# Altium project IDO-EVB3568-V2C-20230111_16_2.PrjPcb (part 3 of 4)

## Sheet P13.SchDoc
size 420 x 297 mm
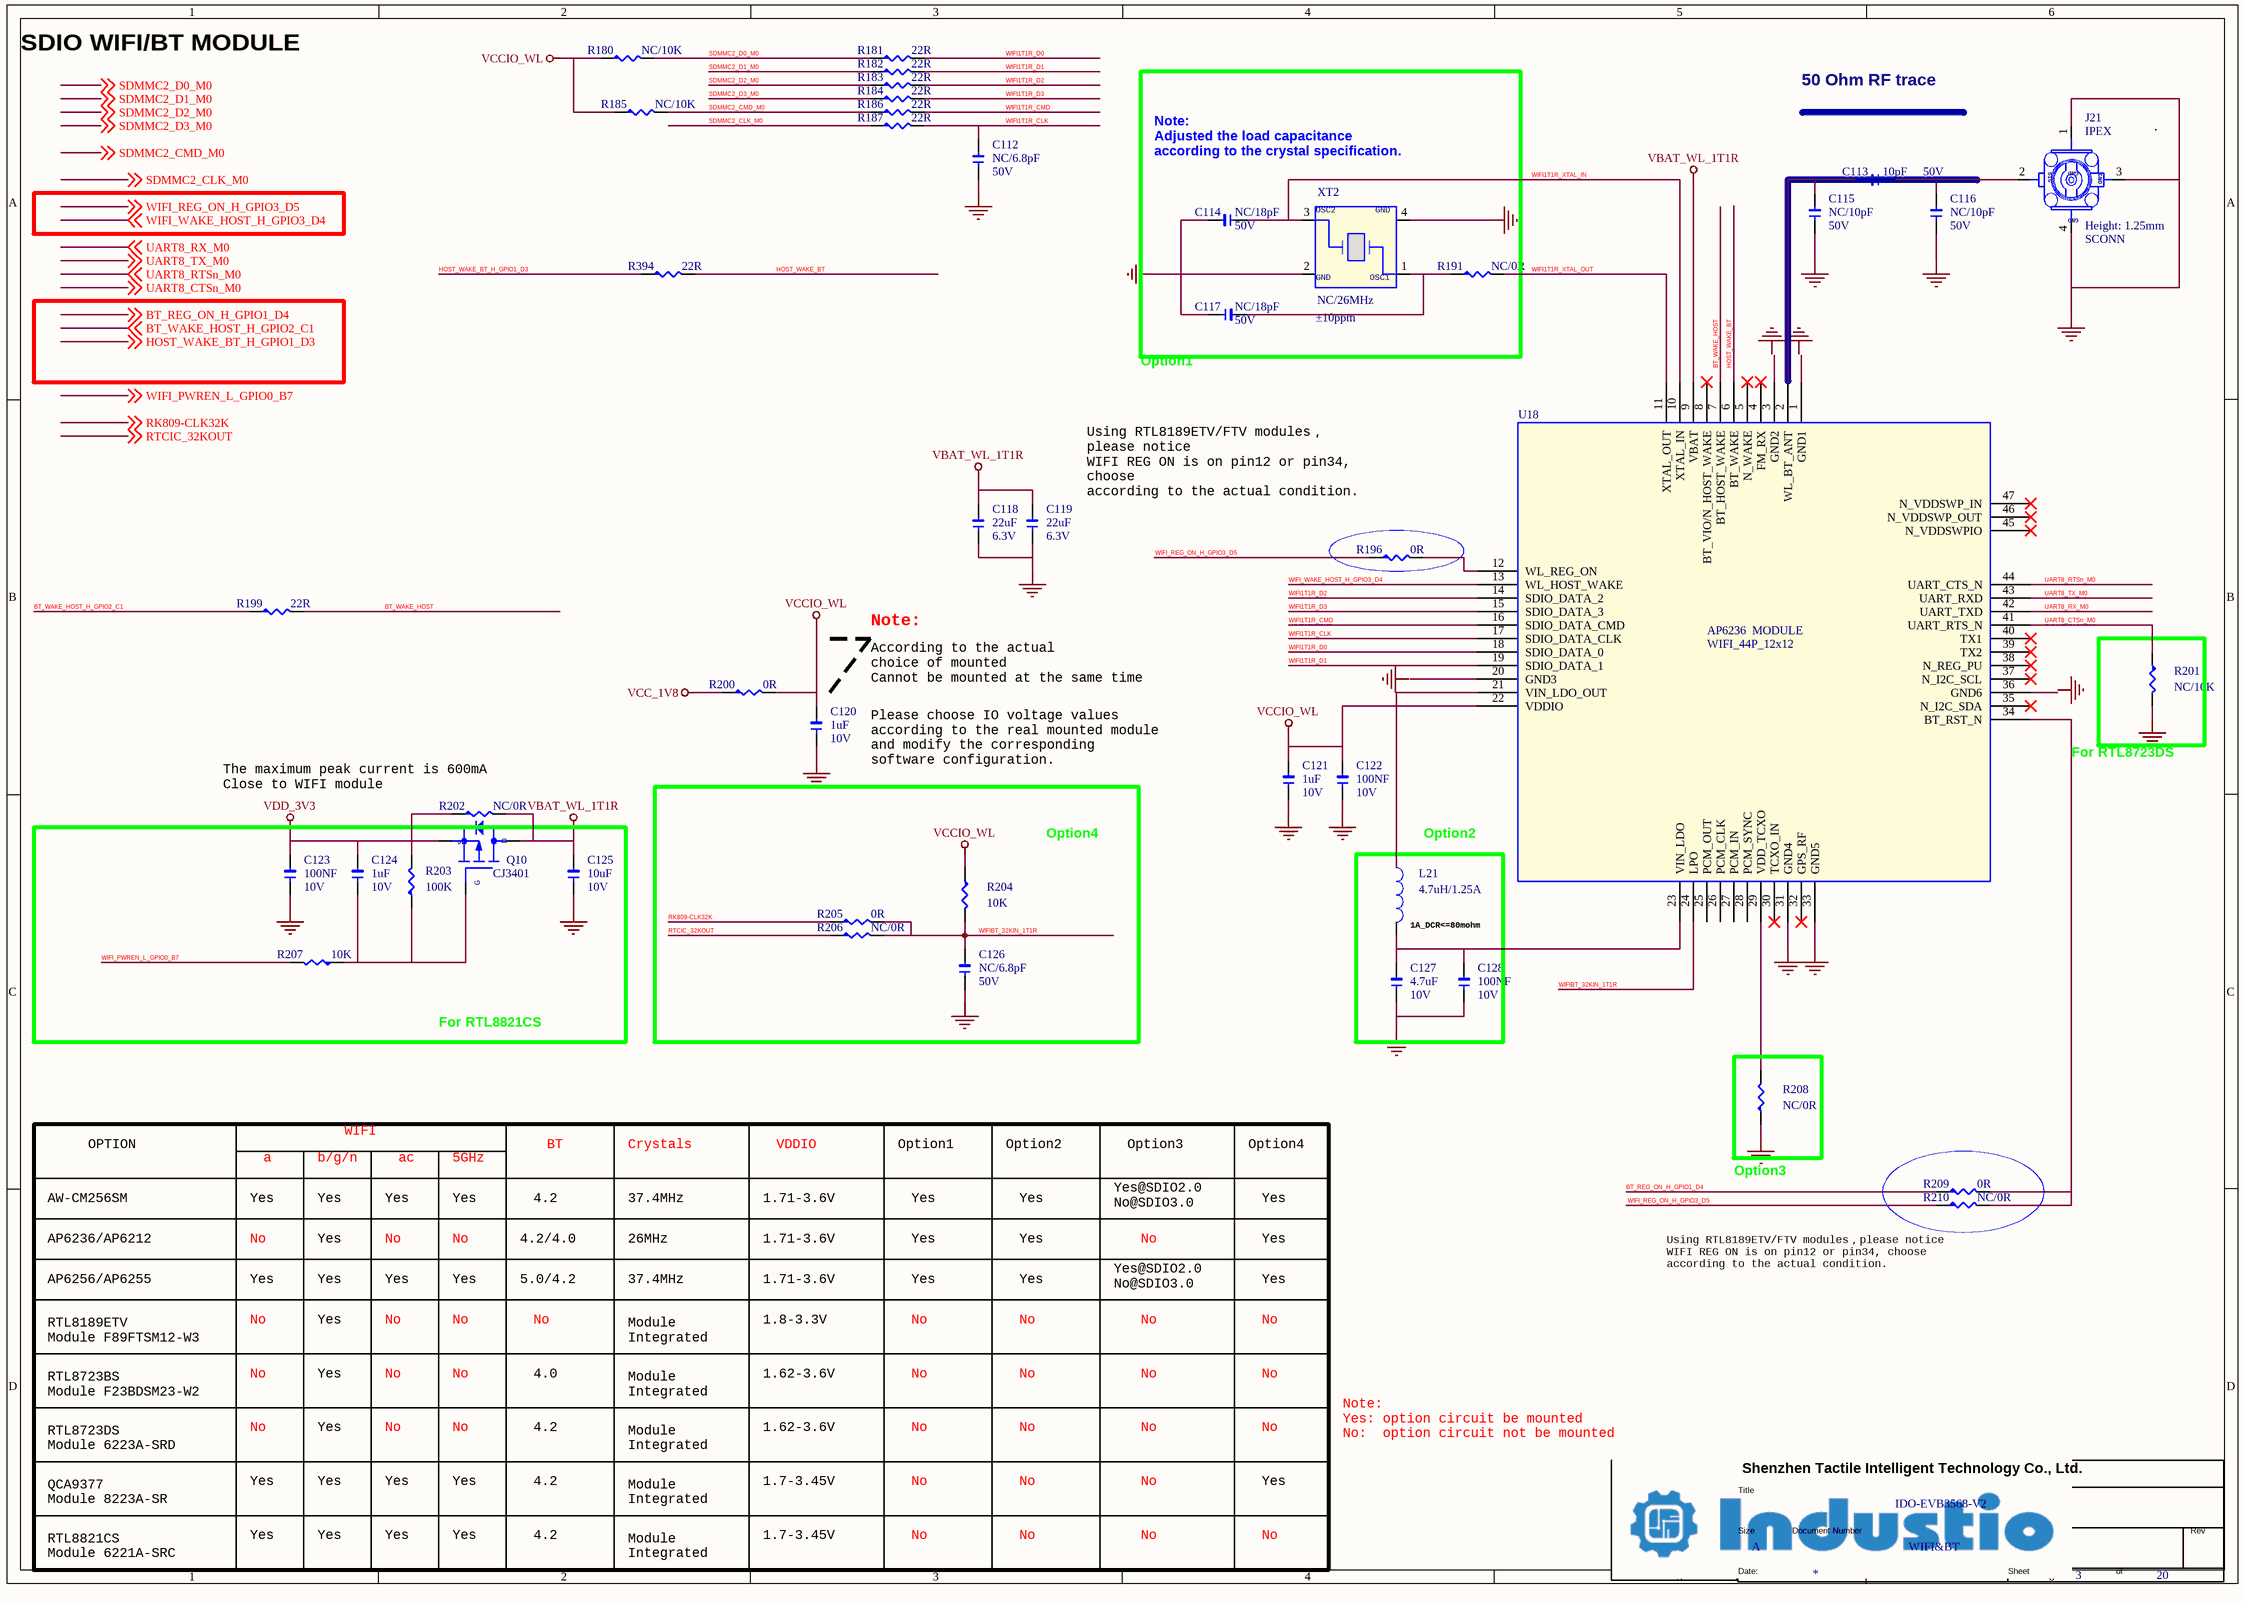
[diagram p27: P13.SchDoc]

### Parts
(Parts that share a designator on the sheet are numbered #1, #2 ... from top to bottom, then left to right.)
*#12  Doc: WIFI&BT  Title: IDO-EVB3568-V2  Page Size: A  Page Number: 3  Page Count: 20  (hidden comment: TitleBlock1)  (graphical)
C112  NC/6.8pF  DSC2: 50V  [1206]
C113  10pF  DSC2: 50V  [1206]
C114  NC/18pF  DSC2: 50V  [1206]
C115  NC/10pF  DSC2: 50V  [1206]
C116  NC/10pF  DSC2: 50V  [1206]
C117  NC/18pF  DSC2: 50V  [1206]
C118  22uF  DSC2: 6.3V  [1206]
C119  22uF  DSC2: 6.3V  [1206]
C120  1uF  DSC2: 10V  [1206]
C121  1uF  DSC2: 10V  [1206]
C122  100NF  DSC2: 10V  [1206]
C123  100NF  DSC2: 10V  [1206]
C124  1uF  DSC2: 10V  [1206]
C125  10uF  DSC2: 10V  [1206]
C126  NC/6.8pF  DSC2: 50V  [1206]
C127  4.7uF  DSC2: 10V  [1206]
C128  100NF  DSC2: 10V  [1206]
J21  IPEX  Material: SCONN  Height: 1.25mm  [IPEX-001E]
L21  4.7uH/1.25A  [IND_252012]
Q10  CJ3401  [SOT23]
R180  NC/10K  [R0402]
R181  22R  [R0402]
R182  22R  [R0402]
R183  22R  [R0402]
R184  22R  [R0402]
R185  NC/10K  [R0402]
R186  22R  [R0402]
R187  22R  [R0402]
R191  NC/0R  [R0402]
R196  0R  [R0402]
R199  22R  [R0402]
R200  0R  [R0402]
R201  NC/10K  [R0402]
R202  NC/0R  [R0805]
R203  100K  [R0402]
R204  10K  [R0402]
R205  0R  [R0402]
R206  NC/0R  [R0402]
R207  10K  [R0402]
R208  NC/0R  [R0402]
R209  0R  [R0402]
R210  NC/0R  [R0402]
R394  22R  [R0402]
U18  AP6236  MODULE  [WIFI_44P_12x12]
XT2  NC/26MHz  DSC2: ±10ppm  [XTAL_32X25_4P]

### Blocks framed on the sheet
Option4: C126 R204-R206
For RTL8821CS: C123-C125 Q10 R203 R207
Option2: C127 C128 L21

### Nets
GND: C112.1 C114.2 C115.1 C116.1 C117.1 C118.1 C119.1 C120.1 C121.1 C122.1 C123.1 C125.1 C126.1 C127.1 C128.1 J21.1(GND1) J21.3(GND2) J21.4(GND3) R201.2 R208.1 U18.31(GND4) U18.33(GND5) XT2.2 XT2.4  [project net EDP_TX_AUXP_]
RTCIC_32KOUT: R206.1 ; off-sheet RTCIC_32KOUT  [project net I2C_SCL_RTC]
VBAT_WL_1T1R: C118.2 C119.2 C125.2 Q10.3(DRAIN) R202.2 U18.9(VBAT)
VCC_1V8: R200.1
VCCIO_WL: C120.2 C121.2 C122.2 R180.1 R185.1 R200.2 R204.1 U18.22(VDDIO)
VDD_3V3: C123.2 C124.2 Q10.2(SOURCE) R202.1 R203.2
BT_REG_ON_H_GPIO1_D4: R209.1 ; off-sheet BT_REG_ON_H_GPIO1_D4
BT_WAKE_HOST: R199.2 U18.7(BT_HOST_WAKE)
BT_WAKE_HOST_H_GPIO2_C1: R199.1 ; off-sheet BT_WAKE_HOST_H_GPIO2_C1
HOST_WAKE_BT: R394.2 U18.6(BT_WAKE)
HOST_WAKE_BT_H_GPIO1_D3: R394.1 ; off-sheet HOST_WAKE_BT_H_GPIO1_D3
RK809-CLK32K: R205.1 ; off-sheet RK809-CLK32K
SDMMC2_CLK_M0: R187.1 ; off-sheet SDMMC2_CLK_M0
SDMMC2_CMD_M0: R185.2 R186.1 ; off-sheet SDMMC2_CMD_M0
SDMMC2_D0_M0: R180.2 R181.1 ; off-sheet SDMMC2_D0_M0
SDMMC2_D1_M0: R182.1 ; off-sheet SDMMC2_D1_M0
SDMMC2_D2_M0: R183.1 ; off-sheet SDMMC2_D2_M0
SDMMC2_D3_M0: R184.1 ; off-sheet SDMMC2_D3_M0
UART8_CTSn_M0: R201.1 U18.41(UART_RTS_N) ; off-sheet UART8_CTSn_M0
UART8_RTSn_M0: U18.44(UART_CTS_N) ; off-sheet UART8_RTSn_M0
UART8_RX_M0: U18.42(UART_TXD) ; off-sheet UART8_RX_M0
UART8_TX_M0: U18.43(UART_RXD) ; off-sheet UART8_TX_M0
WIFI1T1R_CLK: C112.2 R187.2 U18.17(SDIO_DATA_CLK)
WIFI1T1R_CMD: R186.2 U18.16(SDIO_DATA_CMD)
WIFI1T1R_D0: R181.2 U18.18(SDIO_DATA_0)
WIFI1T1R_D1: R182.2 U18.19(SDIO_DATA_1)
WIFI1T1R_D2: R183.2 U18.14(SDIO_DATA_2)
WIFI1T1R_D3: R184.2 U18.15(SDIO_DATA_3)
WIFI1T1R_XTAL_IN: C114.1 U18.10(XTAL_IN) XT2.3
WIFI1T1R_XTAL_OUT: R191.2 U18.11(XTAL_OUT)
WIFI_PWREN_L_GPIO0_B7: R207.2 ; off-sheet WIFI_PWREN_L_GPIO0_B7
WIFI_REG_ON_H_GPIO3_D5: R196.1 R210.1 ; off-sheet WIFI_REG_ON_H_GPIO3_D5
WIFI_WAKE_HOST_H_GPIO3_D4: U18.13(WL_HOST_WAKE) ; off-sheet WIFI_WAKE_HOST_H_GPIO3_D4
WIFIBT_32KIN_1T1R: C126.2 R204.2 R205.2 R206.2 U18.24(LPO)
NetC113_1: C113.1 C116.2 J21.2(SIG)
NetC113_2: C113.2 C115.2 U18.2(WL_BT_ANT)
NetC117_2: C117.2 R191.1 XT2.1
NetC124_1: C124.1 Q10.1(GATE) R203.1 R207.1
NetC127_2: C127.2 C128.2 L21.2 U18.23(VIN_LDO)
NetL21_1: L21.1 U18.21(VIN_LDO_OUT)
NetR196_2: R196.2 U18.12(WL_REG_ON)
NetR208_2: R208.2 U18.29(VDD_TCXO)
NetR209_2: R209.2 R210.2 U18.34(BT_RST_N)

Not connected (* = marked no-connect by the designer): U18 1(GND1) 3(GND2) 4(FM_RX)* 5(N_WAKE)* 8(BT_VIO/N_HOST_WAKE)* 20(GND3) 25(PCM_OUT) 26(PCM_CLK) 27(PCM_IN) 28(PCM_SYNC) 30(TCXO_IN)* 32(GPS_RF)* 35(N_I2C_SDA)* 36(GND6) 37(N_I2C_SCL)* 38(N_REG_PU)* 39(TX2)* 40(TX1)* 45(N_VDDSWPIO)* 46(N_VDDSWP_OUT)* 47(N_VDDSWP_IN)*

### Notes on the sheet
- SDIO WIFI/BT MODULE
- Note:
  Adjusted the load capacitance
  according to the crystal specification.
- 50 Ohm RF trace
- (near C117) Option1
- Using RTL8189ETV/FTV modules，
  please notice
  WIFI REG ON is on pin12 or pin34,
  choose
  according to the actual condition.
- According to the actual
  choice of mounted
  Cannot be mounted at the same time
- Note:
- (near C121) Please choose IO voltage values
  according to the real mounted module
  and modify the corresponding
  software configuration.
- (near R202) The maximum peak current is 600mA
  Close to WIFI module
- For RTL8723DS
- (near L21) 1A_DCR<=80mohm
- WIFI
- AW-CM256SM
- OPTION
- Yes
- a
- b/g/n
- ac
- 5GHz
- 4.2
- BT
- Crystals
- 37.4MHz
- 1.71-3.6V
- VDDIO
- Option1
- Option2
- Yes@SDIO2.0
  No@SDIO3.0
- Option3
- Option4
- AP6236/AP6212
- No
- 4.2/4.0
- 26MHz
- Using RTL8189ETV/FTV modules，please notice
  WIFI REG ON is on pin12 or pin34, choose
  according to the actual condition.
- AP6256/AP6255
- RTL8189ETV
  Module F89FTSM12-W3
- 5.0/4.2
- Module
  Integrated
- 1.8-3.3V
- RTL8723BS
  Module F23BDSM23-W2
- 4.0
- 1.62-3.6V
- (near *#12) Note:
  Yes: option circuit be mounted
  No:  option circuit not be mounted
- RTL8723DS
  Module 6223A-SRD
- QCA9377
  Module 8223A-SR
- RTL8821CS
  Module 6221A-SRC
- 1.7-3.45V
- Labels drawn without touching a wire or pin: GND

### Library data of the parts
C112 = C-0402_Dup2: Part Number: C020102120018; Part Name: 贴片电容; Manufacture: 三星¦国巨¦村田; ERP Number: 1010200056; DSC1: ±0.25PF; DSC3: C0G; ID: 18; PCB Footprint: C0402
C113 = C-0402_Dup2: Manufacture: 三星¦国巨¦村田; Part Name: 贴片电容; Part Number: C020102120021; ID: 21; DSC3: C0G; DSC1: ±5%; ERP Number: 1010200151; PCB Footprint: C0402
C114 C117 = C-0402_Dup2: Manufacture: 三星¦国巨¦村田; Part Name: 贴片电容; Part Number: C020102120027; PCB Footprint: C0402; ID: 27; DSC3: C0G; DSC1: ±5%; ERP Number: 1010200091
C115 C116 = C-0402_Dup2: Part Number: C020102120021; Part Name: 贴片电容; Manufacture: 三星¦国巨¦村田; ERP Number: 1010200151; DSC1: ±5%; DSC3: C0G; ID: 21; PCB Footprint: C0402
C118 C119 = C-0603_Dup2: Manufacture: 三星¦国巨¦村田; Part Name: 贴片电容; Part Number: C020102120072; ID: 72; DSC3: X5R; DSC1: ±20%; ERP Number: 1010200133; PCB Footprint: C0603
C120 C124 = C-0402_Dup2: Part Number: C020102120064; Part Name: 贴片电容; Manufacture: 三星¦国巨¦村田; ERP Number: 1010200054; DSC1: ±10%; DSC3: X5R; ID: 64; PCB Footprint: C0402
C121 = C-0402_Dup2: Manufacture: 三星¦国巨¦村田; Part Name: 贴片电容; Part Number: C020102120064; ID: 64; DSC3: X5R; DSC1: ±10%; ERP Number: 1010200054; PCB Footprint: C0402
C122 C128 = C-0402_Dup2: Manufacture: 三星¦国巨¦村田; Part Name: 贴片电容; Part Number: C020102120060; ID: 60; DSC3: X7R; DSC1: ±10%; PCB Footprint: C0402
C123 = C-0402_Dup2: Part Number: C020102120060; Part Name: 贴片电容; Manufacture: 三星¦国巨¦村田; DSC1: ±10%; DSC3: X7R; ID: 60; PCB Footprint: C0402
C125 = C-0603_Dup2: Manufacture: 三星¦国巨¦村田; Part Name: 贴片电容; Part Number: C020102120071; ID: 71; DSC3: X5R; DSC1: ±20%; ERP Number: 1010200076; PCB Footprint: C0603
C126 = C-0402_Dup2: Manufacture: 三星¦国巨¦村田; Part Name: 贴片电容; Part Number: C020102120018; ID: 18; DSC3: C0G; DSC1: ±0.25PF; ERP Number: 1010200056; PCB Footprint: C0402
C127 = C-0402_Dup2: Manufacture: 三星¦国巨¦村田; Part Name: 贴片电容; Part Number: C020102120067; ID: 67; DSC3: X5R; DSC1: ±20%; PCB Footprint: C0402
J21 = RF-IPEX-20279: SMD micro Coaxial Connector Receptacle vertial; Part Name: IPEX座; Part Number: J110103040001; Pack_Type: MHF-20279; ID: 1; DSC2: 贴片; DSC1: IPEX-20279-001E-01 板端贴片天线座 U.LF接头
L21 = L-IND: Part Name: 功率电感; Manufacture: 宗成¦长江微电¦顺络; DSC1: ±20%; DSC2: Isat=1.6A; DSC3: Irms=1.25A; DSC4: 260mΩ; DSC5: 2.5*2.0*1.2mm; DSC6: WPN252012H4R7MT(顺络); DSC7: FHD252012S-4R7MT(长江微电); DSC8: ZCRH252012-4.7uH-M(宗成); ID: 54
Q10 = P-MOS: Manufacture: 长电; Part Number: C030202190001; ID: 1; DSC5: pd=350mW; DSC4: Vgs=±12V; DSC3: Vgs(th)=1.3V; DSC2: Id=-4.2A; DSC1: Vds=-30V; ERP Number: 1010800001
R180 R185 R201 R204 R207 = R-0402_Dup4: Part Name: 贴片电阻; Part Number: C011002080328; ERP Number: 1010200096; DSC1: ±5%; DSC2: 1/16W; ID: 328
R181-R184 R186 R187 R199 R394 = R-0402_Dup4: Part Number: C011002080262; Part Name: 贴片电阻; ID: 262; DSC2: 1/16W; DSC1: ±5%; ERP Number: 1010200173
R191 R196 R200 R206 R209 = R-0402_Dup4: Part Number: C011002080217; Part Name: 贴片电阻; ID: 217; DSC2: 1/16W; DSC1: ±5%; ERP Number: 1010200100
R202 = R-0805_Dup2: Part Number: C011002081448; Part Name: 贴片电阻; ID: 1,448; DSC2: 1/8W; DSC1: ±1%; ERP Number: 1010200199
R203 = R-0402_Dup4: Part Number: C011002080353; Part Name: 贴片电阻; ID: 353; DSC2: 1/16W; DSC1: ±5%; ERP Number: 1010200103
R205 R208 R210 = R-0402_Dup4: Part Name: 贴片电阻; Part Number: C011002080217; ERP Number: 1010200100; DSC1: ±5%; DSC2: 1/16W; ID: 217
U18 = MODULE_AP6XXX: WiFi+Bluetooth 4.0(HS)+FM Rx; Manufacturer PN: AP6335; Manufacturer: Ampak（正基科技）; Priority: A
XT2 = XTAL-4P: Manufacture: 爱普生; Part Number: C050102290007; Part Name: 贴片无源晶振; CLASS: IC; ID: 7; DSC5: 3.2*2.5mm 4P; DSC4: -40℃~+85℃; DSC3: 12pF; DSC1: 40Ω; ERP Number: 1010700036

## Sheet P14.SchDoc
size 594 x 420 mm
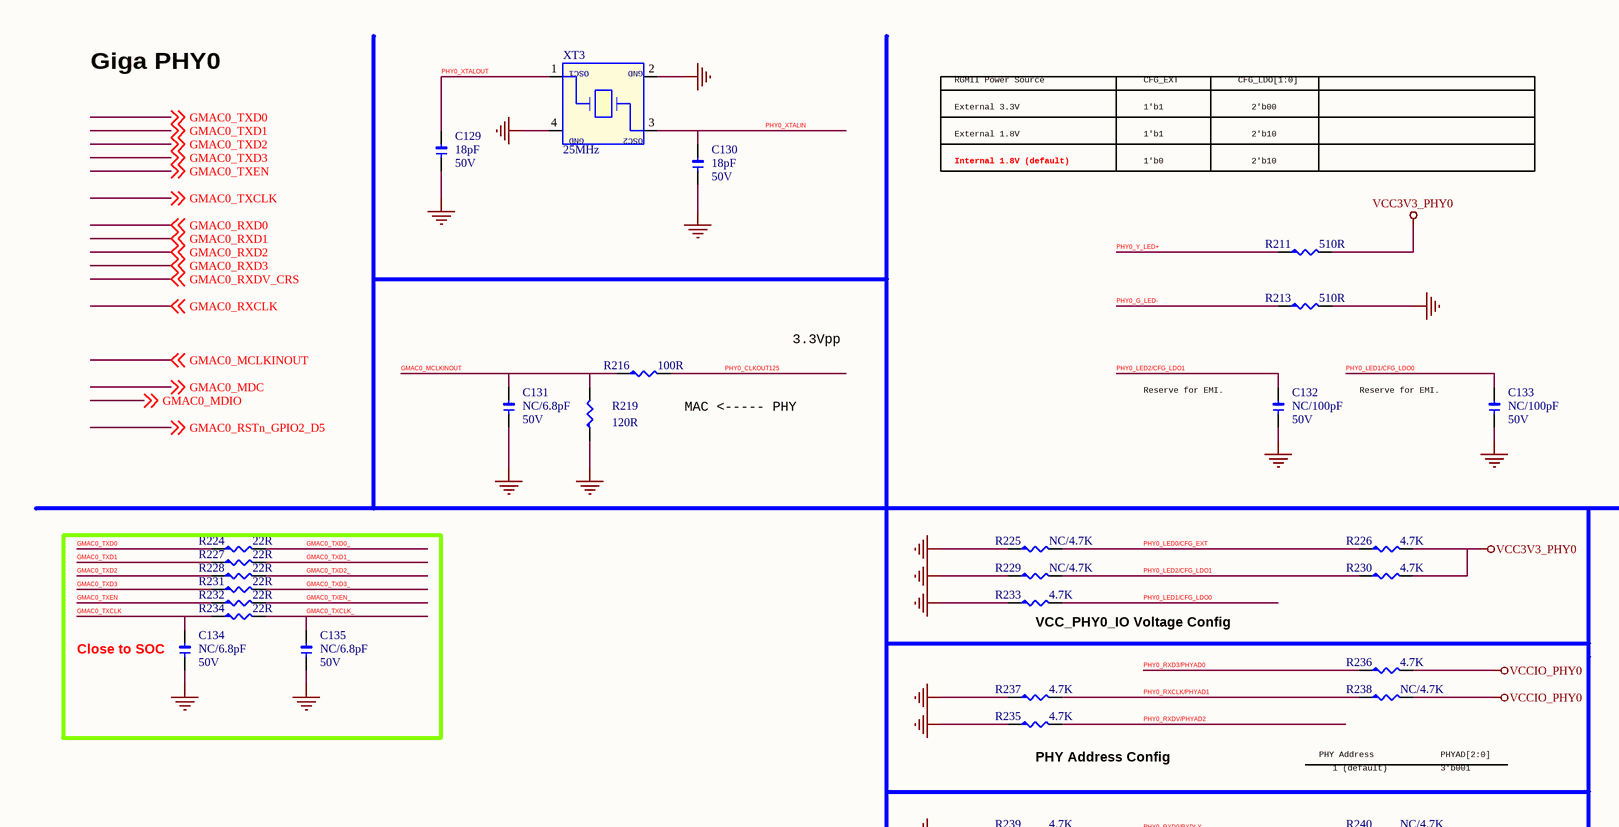
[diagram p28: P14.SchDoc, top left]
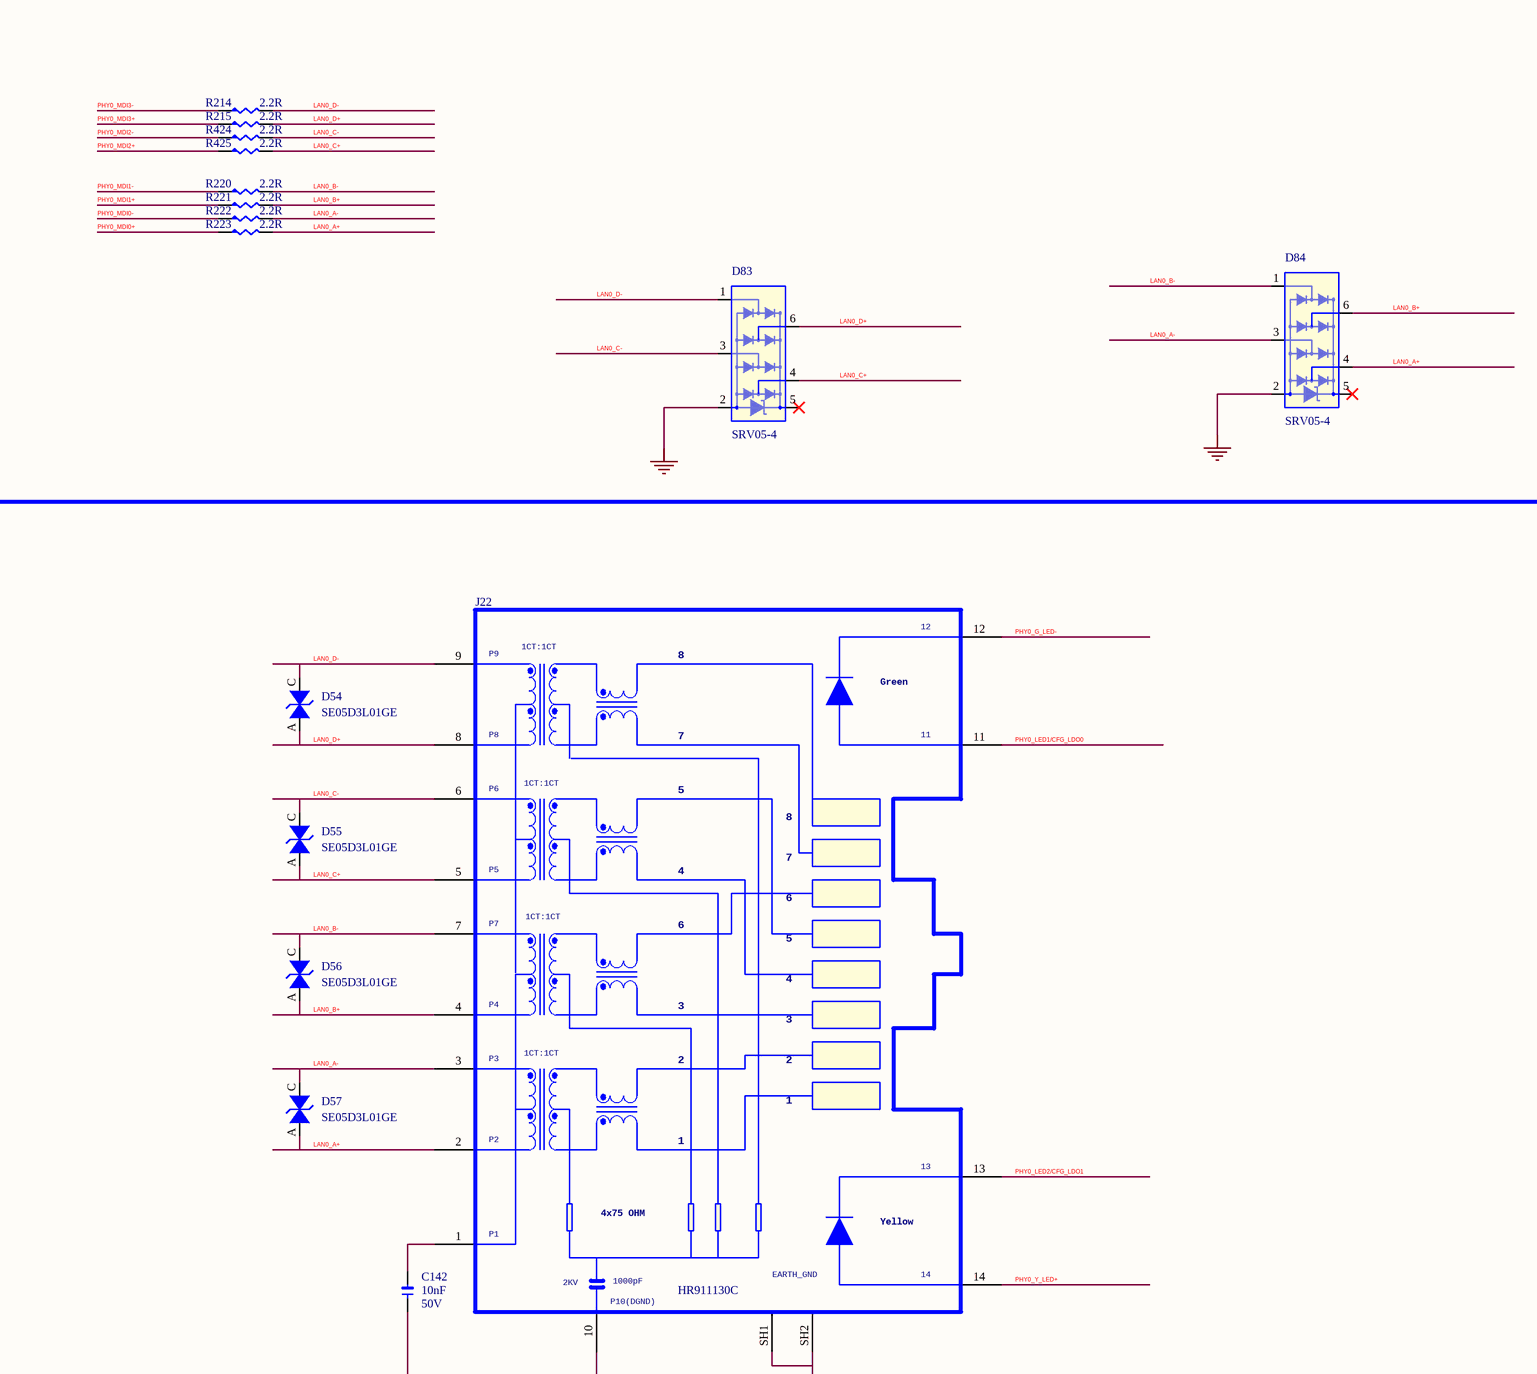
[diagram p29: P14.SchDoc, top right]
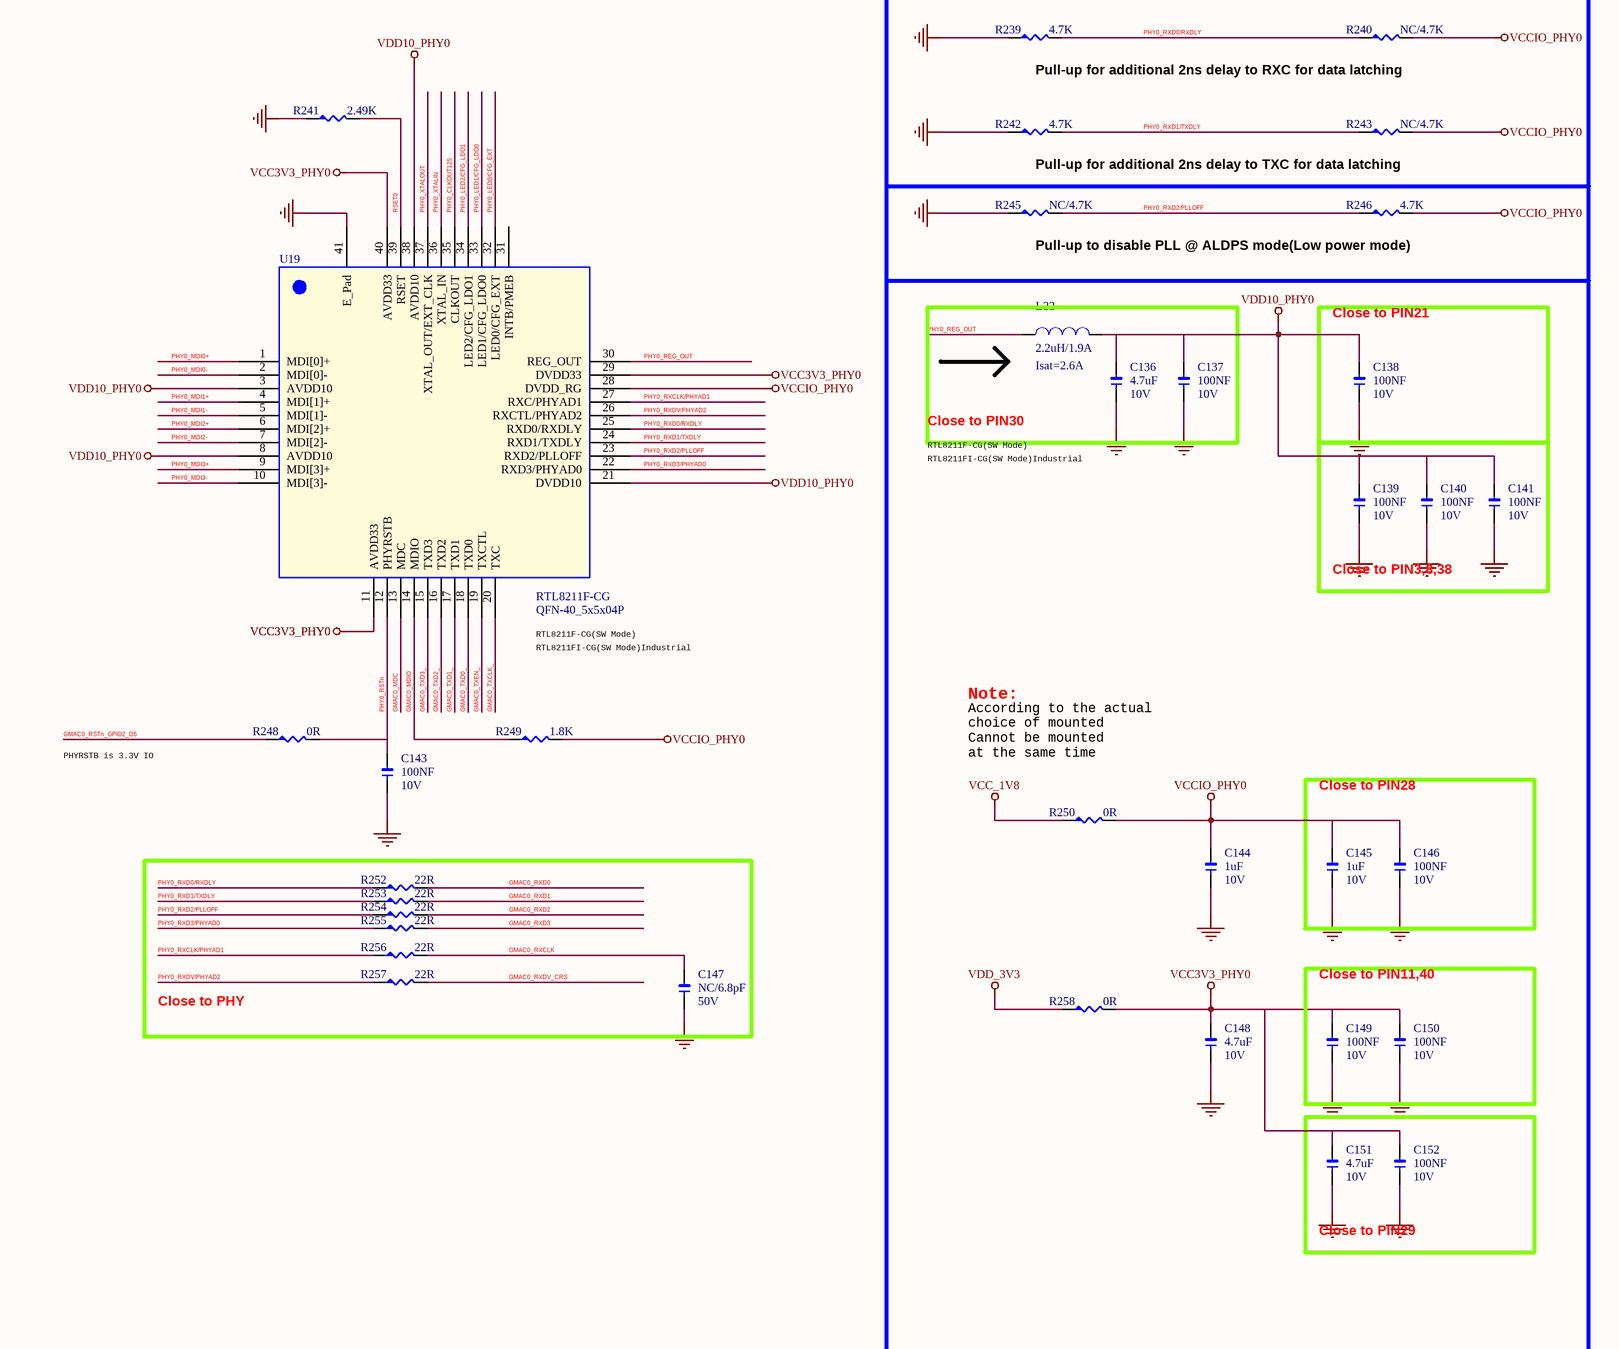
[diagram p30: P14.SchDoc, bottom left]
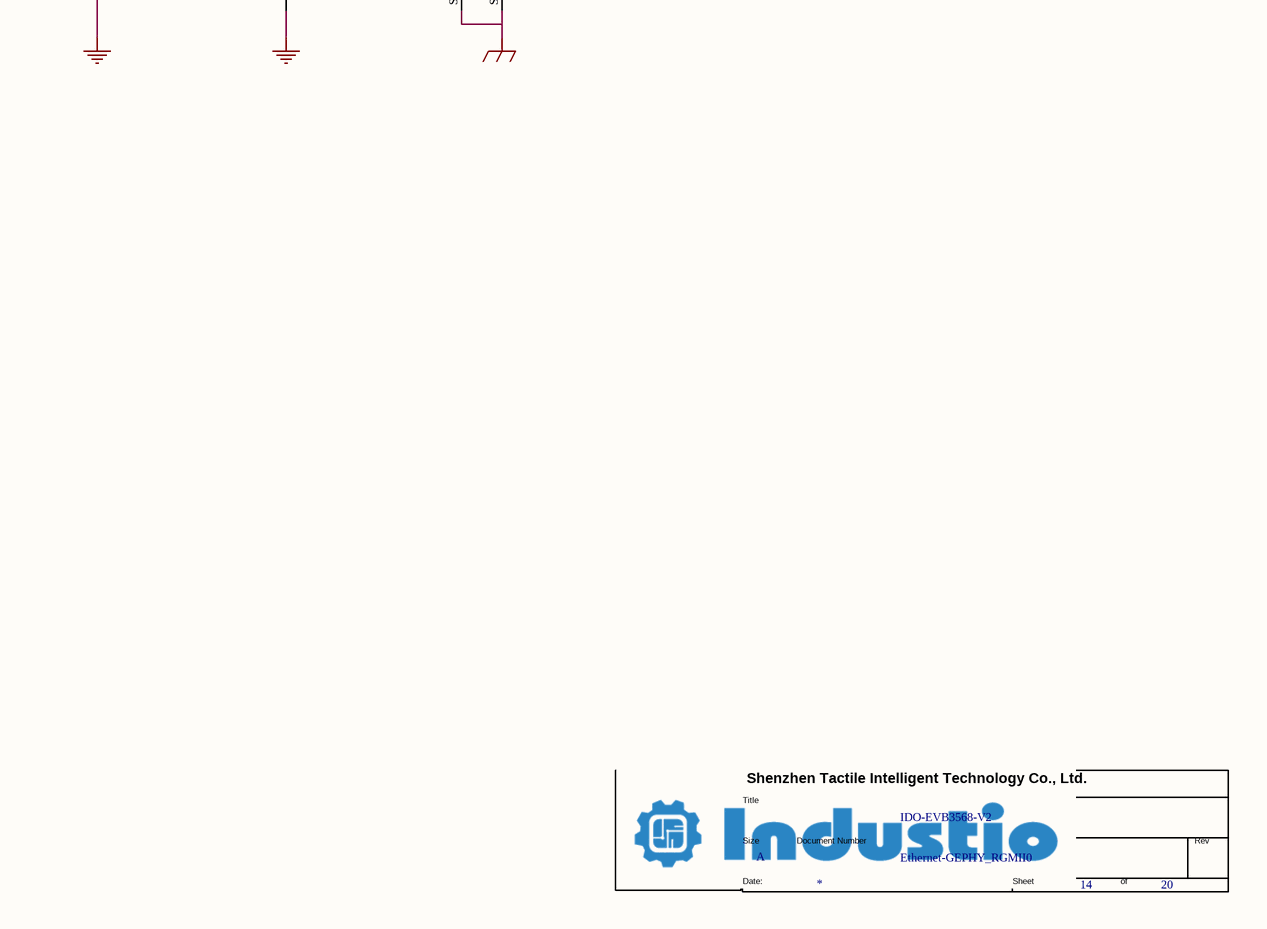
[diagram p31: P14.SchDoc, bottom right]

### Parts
(Parts that share a designator on the sheet are numbered #1, #2 ... from top to bottom, then left to right.)
*#13  Doc: Ethernet-GEPHY_RGMII0  Title: IDO-EVB3568-V2  Page Size: A  Page Number: 14  Page Count: 20  (hidden comment: TitleBlock1)  (graphical)
C129  18pF  DSC2: 50V  [1206]
C130  18pF  DSC2: 50V  [1206]
C131  NC/6.8pF  DSC2: 50V  [1206]
C132  NC/100pF  DSC2: 50V  [1206]
C133  NC/100pF  DSC2: 50V  [1206]
C134  NC/6.8pF  DSC2: 50V  [1206]
C135  NC/6.8pF  DSC2: 50V  [1206]
C136  4.7uF  DSC2: 10V  [1206]
C137  100NF  DSC2: 10V  [1206]
C138  100NF  DSC2: 10V  [1206]
C139  100NF  DSC2: 10V  [1206]
C140  100NF  DSC2: 10V  [1206]
C141  100NF  DSC2: 10V  [1206]
C142  10nF  DSC2: 50V  [1206]
C143  100NF  DSC2: 10V  [1206]
C144  1uF  DSC2: 10V  [1206]
C145  1uF  DSC2: 10V  [1206]
C146  100NF  DSC2: 10V  [1206]
C147  NC/6.8pF  DSC2: 50V  [1206]
C148  4.7uF  DSC2: 10V  [1206]
C149  100NF  DSC2: 10V  [1206]
C150  100NF  DSC2: 10V  [1206]
C151  4.7uF  DSC2: 10V  [1206]
C152  100NF  DSC2: 10V  [1206]
D54  SE05D3L01GE  [SOD323]
D55  SE05D3L01GE  [SOD323]
D56  SE05D3L01GE  [SOD323]
D57  SE05D3L01GE  [SOD323]
D83  SRV05-4  [SOT23-6]
D84  SRV05-4  [SOT23-6]
J22  HR911130C  [RJ45-TH_HR911130A]
L22  2.2uH/1.9A  DSC2: Isat=2.6A  [IND_252012]
R211  510R  [R0402]
R213  510R  [R0402]
R214  2.2R  [R0402]
R215  2.2R  [R0402]
R216  100R  [R0402]
R219  120R  [R0402]
R220  2.2R  [R0402]
R221  2.2R  [R0402]
R222  2.2R  [R0402]
R223  2.2R  [R0402]
R224  22R  [R0402]
R225  NC/4.7K  [R0402]
R226  4.7K  [R0402]
R227  22R  [R0402]
R228  22R  [R0402]
R229  NC/4.7K  [R0402]
R230  4.7K  [R0402]
R231  22R  [R0402]
R232  22R  [R0402]
R233  4.7K  [R0402]
R234  22R  [R0402]
R235  4.7K  [R0402]
R236  4.7K  [R0402]
R237  4.7K  [R0402]
R238  NC/4.7K  [R0402]
R239  4.7K  [R0402]
R240  NC/4.7K  [R0402]
R241  2.49K  [R0402]
R242  4.7K  [R0402]
R243  NC/4.7K  [R0402]
R245  NC/4.7K  [R0402]
R246  4.7K  [R0402]
R248  0R  [R0402]
R249  1.8K  [R0402]
R250  0R  [R0402]
R252  22R  [R0402]
R253  22R  [R0402]
R254  22R  [R0402]
R255  22R  [R0402]
R256  22R  [R0402]
R257  22R  [R0402]
R258  0R  [R0402]
R424  2.2R  [R0402]
R425  2.2R  [R0402]
U19  RTL8211F-CG  PCB Footprint: QFN-40_5x5x04P  [QFN40_5R00X5R00X0R80_T]
XT3  25MHz  [xtal_32x25_4p]

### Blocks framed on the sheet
Close to SOC: C134 C135 R224 R227 R228 R231 R232 R234
Close to PIN30: C136 C137 L22
Close to PIN21: C138
Close to PIN3,8,38: C139-C141
Close to PIN28: C145 C146
Close to PHY: C147 R252-R257
Close to PIN11,40: C149 C150
Close to PIN29: C151 C152

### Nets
GND: C129.1 C130.1 C131.1 C132.1 C133.1 C134.1 C135.1 C136.1 C137.1 C138.1 C139.1 C140.1 C141.1 C142.1 C143.1 C144.1 C145.1 C146.1 C147.1 C148.1 C149.1 C150.1 C151.1 C152.1 D83.2 D84.2 J22.10(GND) R213.2 R219.1 R225.1 R229.1 R233.1 R235.1 R237.1 R239.1 R241.1 R242.1 R245.1 U19.41(E_Pad) XT3.2 XT3.4  [project net EDP_TX_AUXP_]
GND_EARTH: J22.SH1 J22.SH2
VCC3V3_PHY0: C148.2 C149.2 C150.2 C151.2 C152.2 R211.2 R226.2 R230.2 R258.2 U19.11(AVDD33) U19.29(DVDD33) U19.40(AVDD33)
VCC_1V8: R250.1
VCCIO_PHY0: C144.2 C145.2 C146.2 R236.2 R238.2 R240.2 R243.2 R246.2 R249.2 R250.2 U19.28(DVDD_RG)
VDD10_PHY0: C136.2 C137.2 C138.2 C139.2 C140.2 C141.2 L22.2 U19.3(AVDD10) U19.8(AVDD10) U19.21(DVDD10) U19.38(AVDD10)
VDD_3V3: R258.1
GMAC0_MCLKINOUT: C131.2 R216.1 R219.2 ; off-sheet GMAC0_MCLKINOUT
GMAC0_MDC: U19.13(MDC) ; off-sheet GMAC0_MDC
GMAC0_MDIO: R249.1 U19.14(MDIO) ; off-sheet GMAC0_MDIO
GMAC0_RSTn_GPIO2_D5: R248.1 ; off-sheet GMAC0_RSTn_GPIO2_D5
GMAC0_RXCLK: C147.2 R256.2 ; off-sheet GMAC0_RXCLK
GMAC0_RXD0: R252.2 ; off-sheet GMAC0_RXD0
GMAC0_RXD1: R253.2 ; off-sheet GMAC0_RXD1
GMAC0_RXD2: R254.2 ; off-sheet GMAC0_RXD2
GMAC0_RXD3: R255.2 ; off-sheet GMAC0_RXD3
GMAC0_RXDV_CRS: R257.2 ; off-sheet GMAC0_RXDV_CRS
GMAC0_TXCLK: C134.2 R234.1 ; off-sheet GMAC0_TXCLK
GMAC0_TXCLK_: C135.2 R234.2 U19.20(TXC)
GMAC0_TXD0: R224.1 ; off-sheet GMAC0_TXD0
GMAC0_TXD0_: R224.2 U19.18(TXD0)
GMAC0_TXD1: R227.1 ; off-sheet GMAC0_TXD1
GMAC0_TXD1_: R227.2 U19.17(TXD1)
GMAC0_TXD2: R228.1 ; off-sheet GMAC0_TXD2
GMAC0_TXD2_: R228.2 U19.16(TXD2)
GMAC0_TXD3: R231.1 ; off-sheet GMAC0_TXD3
GMAC0_TXD3_: R231.2 U19.15(TXD3)
GMAC0_TXEN: R232.1 ; off-sheet GMAC0_TXEN
GMAC0_TXEN_: R232.2 U19.19(TXCTL)
LAN0_A+: D57.A(I/O2) D84.4 J22.2(MDI_0+) R223.2
LAN0_A-: D57.C(I/O1) D84.3 J22.3(MDI_0-) R222.2
LAN0_B+: D56.A(I/O2) D84.6 J22.4(MDI_1+) R221.2
LAN0_B-: D56.C(I/O1) D84.1 J22.7(MDI_1-) R220.2
LAN0_C+: D55.A(I/O2) D83.4 J22.5(MDI_2+) R425.2
LAN0_C-: D55.C(I/O1) D83.3 J22.6(MDI_2-) R424.2
LAN0_D+: D54.A(I/O2) D83.6 J22.8(MDI_3+) R215.2
LAN0_D-: D54.C(I/O1) D83.1 J22.9(MDI_3-) R214.2
PHY0_CLKOUT125: R216.2 U19.35(CLKOUT)
PHY0_G_LED-: J22.12(G_LED-) R213.1
PHY0_LED0/CFG_EXT: R225.2 R226.1 U19.32(LED0/CFG_EXT)
PHY0_LED1/CFG_LDO0: C133.2 J22.11(G_LED+) R233.2 U19.33(LED1/CFG_LDO0)
PHY0_LED2/CFG_LDO1: C132.2 J22.13(Y_LED-) R229.2 R230.1 U19.34(LED2/CFG_LDO1)
PHY0_MDI0+: R223.1 U19.1(MDI[0]+)
PHY0_MDI0-: R222.1 U19.2(MDI[0]-)
PHY0_MDI1+: R221.1 U19.4(MDI[1]+)
PHY0_MDI1-: R220.1 U19.5(MDI[1]-)
PHY0_MDI2+: R425.1 U19.6(MDI[2]+)
PHY0_MDI2-: R424.1 U19.7(MDI[2]-)
PHY0_MDI3+: R215.1 U19.9(MDI[3]+)
PHY0_MDI3-: R214.1 U19.10(MDI[3]-)
PHY0_REG_OUT: L22.1 U19.30(REG_OUT)
PHY0_RSTn: C143.2 R248.2 U19.12(PHYRSTB)
PHY0_RXCLK/PHYAD1: R237.2 R238.1 R256.1 U19.27(RXC/PHYAD1)
PHY0_RXD0/RXDLY: R239.2 R240.1 R252.1 U19.25(RXD0/RXDLY)
PHY0_RXD1/TXDLY: R242.2 R243.1 R253.1 U19.24(RXD1/TXDLY)
PHY0_RXD2/PLLOFF: R245.2 R246.1 R254.1 U19.23(RXD2/PLLOFF)
PHY0_RXD3/PHYAD0: R236.1 R255.1 U19.22(RXD3/PHYAD0)
PHY0_RXDV/PHYAD2: R235.2 R257.1 U19.26(RXCTL/PHYAD2)
PHY0_XTALIN: C130.2 U19.36(XTAL_IN) XT3.3
PHY0_XTALOUT: C129.2 U19.37(XTAL_OUT/EXT_CLK) XT3.1
PHY0_Y_LED+: J22.14(Y_LED+) R211.1
RSET0: R241.2 U19.39(RSET)
NetC142_2: C142.2 J22.1(CT1/2/3/4)

Not connected (* = marked no-connect by the designer): D83 5*; D84 5*; U19 31(INTB/PMEB)

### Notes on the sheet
- Giga PHY0
- RGMII Power Source
- External 3.3V
- CFG_EXT
- 1'b1
- CFG_LDO[1:0]
- 2'b00
- External 1.8V
- Internal 1.8V (default)
- 1'b0
- 2'b10
- 3.3Vpp
- (near R216) MAC <----- PHY
- Reserve for EMI.
- (near R233) VCC_PHY0_IO Voltage Config
- (near R235) PHY Address Config
- PHY Address
- 1 (default)
- PHYAD[2:0]
- 3'b001
- Pull-up for additional 2ns delay to RXC for data latching
- Pull-up for additional 2ns delay to TXC for data latching
- Pull-up to disable PLL @ ALDPS mode(Low power mode)
- RTL8211F-CG(SW Mode)
- RTL8211FI-CG(SW Mode)Industrial
- Note:
- (near R250) According to the actual
  choice of mounted
  Cannot be mounted
  at the same time
- PHYRSTB is 3.3V IO

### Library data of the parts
C129 C130 = C-0402_Dup2: Part Number: C020102120027; Part Name: 贴片电容; Manufacture: 三星¦国巨¦村田; ERP Number: 1010200091; DSC1: ±5%; DSC3: C0G; ID: 27; PCB Footprint: C0402
C131 C147 = C-0402_Dup2: as C126 on sheet P13
C132 = C-0402_Dup2: Manufacture: 三星¦国巨¦村田; Part Name: 贴片电容; Part Number: C020102120040; ID: 40; DSC3: C0G; DSC1: ±5%; ERP Number: 1010200152; PCB Footprint: C0402
C133 = C-0402_Dup2: Part Number: C020102120040; Part Name: 贴片电容; Manufacture: 三星¦国巨¦村田; ERP Number: 1010200152; DSC1: ±5%; DSC3: C0G; ID: 40; PCB Footprint: C0402
C134 C135 = C-0402_Dup2: as C112 on sheet P13
C136 = C-0402_Dup2: as C127 on sheet P13
C137-C141 C143 = C-0402_Dup2: as C123 on sheet P13
C142 = C-0402_Dup2: Part Number: C020102120057; Part Name: 贴片电容; Manufacture: 三星¦国巨¦村田; ERP Number: 1010200077; DSC1: ±10%; DSC3: X7R; ID: 57; PCB Footprint: C0402
C144 C145 = C-0402_Dup2: as C120 on sheet P13
C146 C149 C150 C152 = C-0402_Dup2: as C122 on sheet P13
C148 C151 = C-0402_Dup2: Part Number: C020102120067; Part Name: 贴片电容; Manufacture: 三星¦国巨¦村田; DSC1: ±20%; DSC3: X5R; ID: 67; PCB Footprint: C0402
D54 D57 = DI-TVS-D: ESD 0402; Part Number: C040505124709; Manufacture P/N: MLVG04021R0UV18; Manufacturer: INPAQ; Manufacture: 硕凯; PN Type: Varistor; DSC1: 双向; DSC2: Vdc=5V; DSC4: Vc=19V; DSC5: Cj=1.2pF; ID: 10; Solder: 推荐
D55 D56 = DI-TVS-D: ESD 0402; Part Number: C040505124709; Manufacture P/N: MLVG04021R0UV18; Manufacturer: INPAQ; Manufacture: 硕凯; PN Type: Varistor; Solder: 推荐; ID: 10; DSC5: Cj=1.2pF; DSC4: Vc=19V; DSC2: Vdc=5V; DSC1: 双向
D83 = DI-ESD-SRV05-4: Manufacture: 伯恩半导体; Part Name: TVS; Part Number: C040602260015; Solder: 量产; ID: 15; DSC7: Cj=0.36pF; DSC6: Ppp=45W; DSC5: Ipp=3.5A; DSC4: Vc=13V; DSC3: VBR=6V; DSC2: Vrwm=5V; DSC1: 单向; ERP Number: 1010800050
D84 = DI-ESD-SRV05-4: Part Number: C040602260015; Part Name: TVS; Manufacture: 伯恩半导体; ERP Number: 1010800050; DSC1: 单向; DSC2: Vrwm=5V; DSC3: VBR=6V; DSC4: Vc=13V; DSC5: Ipp=3.5A; DSC6: Ppp=45W; DSC7: Cj=0.36pF; ID: 15; Solder: 量产
J22 = J-RJ45-HR911130C: Part Name: RJ45; Part Number: J120103060005; ID: 5; DSC4: HR911130C(汉仁); DSC2: 通孔弯针; DSC1: RJ45 8P插件 内置千兆变压器(商业级)  双灯 卧式 全包带弹片,16x21.3x13.5mm
L22 = L-IND: Manufacture: 宗成¦长江微电¦顺络; Part Name: 功率电感; ID: 53; DSC8: ZCRH252012-2.2uH-M(宗成); DSC7: FHD252012S-2R2MT(长江微电); DSC6: WPN252012H2R2MT(顺络); DSC5: 2.5*2.0*1.2mm; DSC4: 120mΩ; DSC3: Irms=1.9A; DSC1: ±20%
R211 R213 = R-0402_Dup4: Part Name: 贴片电阻; Part Number: C011002080296; ERP Number: 1010200226; DSC1: ±5%; DSC2: 1/16W; ID: 296
R214 R215 R220-R223 R424 R425 = R-0402_Dup4: Part Name: 贴片电阻; Part Number: C011002080238; ERP Number: 1010200263; DSC1: ±5%; DSC2: 1/16W; ID: 238
R216 = R-0402_Dup4: Part Number: C011002080279; Part Name: 贴片电阻; ID: 279; DSC2: 1/16W; DSC1: ±5%; ERP Number: 1010200160
R219 = R-0402_Dup4: Part Number: C011002080281; Part Name: 贴片电阻; ID: 281; DSC2: 1/16W; DSC1: ±5%
R224 R227 R228 R231 R232 R234 R252-R257 = R-0402_Dup4: Part Name: 贴片电阻; Part Number: C011002080262; ERP Number: 1010200173; DSC1: ±5%; DSC2: 1/16W; ID: 262
R225 R229 R238 R240 R243 R245 = R-0402_Dup4: Part Number: C011002080320; Part Name: 贴片电阻; ID: 320; DSC2: 1/16W; DSC1: ±5%; ERP Number: 1010200177
R226 R230 R233 R235-R237 R239 R242 R246 = R-0402_Dup4: Part Name: 贴片电阻; Part Number: C011002080320; ERP Number: 1010200177; DSC1: ±5%; DSC2: 1/16W; ID: 320
R241 = R-0402_Dup5: Part Name: 贴片电阻; Part Number: C011002080785; ERP Number: 1010200324; DSC1: ±1%; DSC2: 1/16W; ID: 785
R248 R258 = R-0402_Dup4: as R205 on sheet P13
R249 = R-0402_Dup4: Part Number: C011002080309; Part Name: 贴片电阻; ID: 309; DSC2: 1/16W; DSC1: ±5%
R250 = R-0402_Dup4: as R191 on sheet P13
U19 = Ethernet_RTL8211F: Integrated 10/100/1000 Gigabit Ethernet Transceiver，Supports IEEE 802.3az-2010,; Manufacturer: RealTek(瑞昱); Priority: A
XT3 = XTAL-4P_Dup1: Manufacture: 泰晶; Part Number: C050102290006; Part Name: 贴片无源晶振; CLASS: IC; ID: 6; DSC5: 3.2*2.5mm 4P; DSC4: -40℃~+85℃; DSC3: 12pF; DSC2: ±10ppm; DSC1: 40Ω

## Sheet P15.SchDoc
size 594 x 420 mm
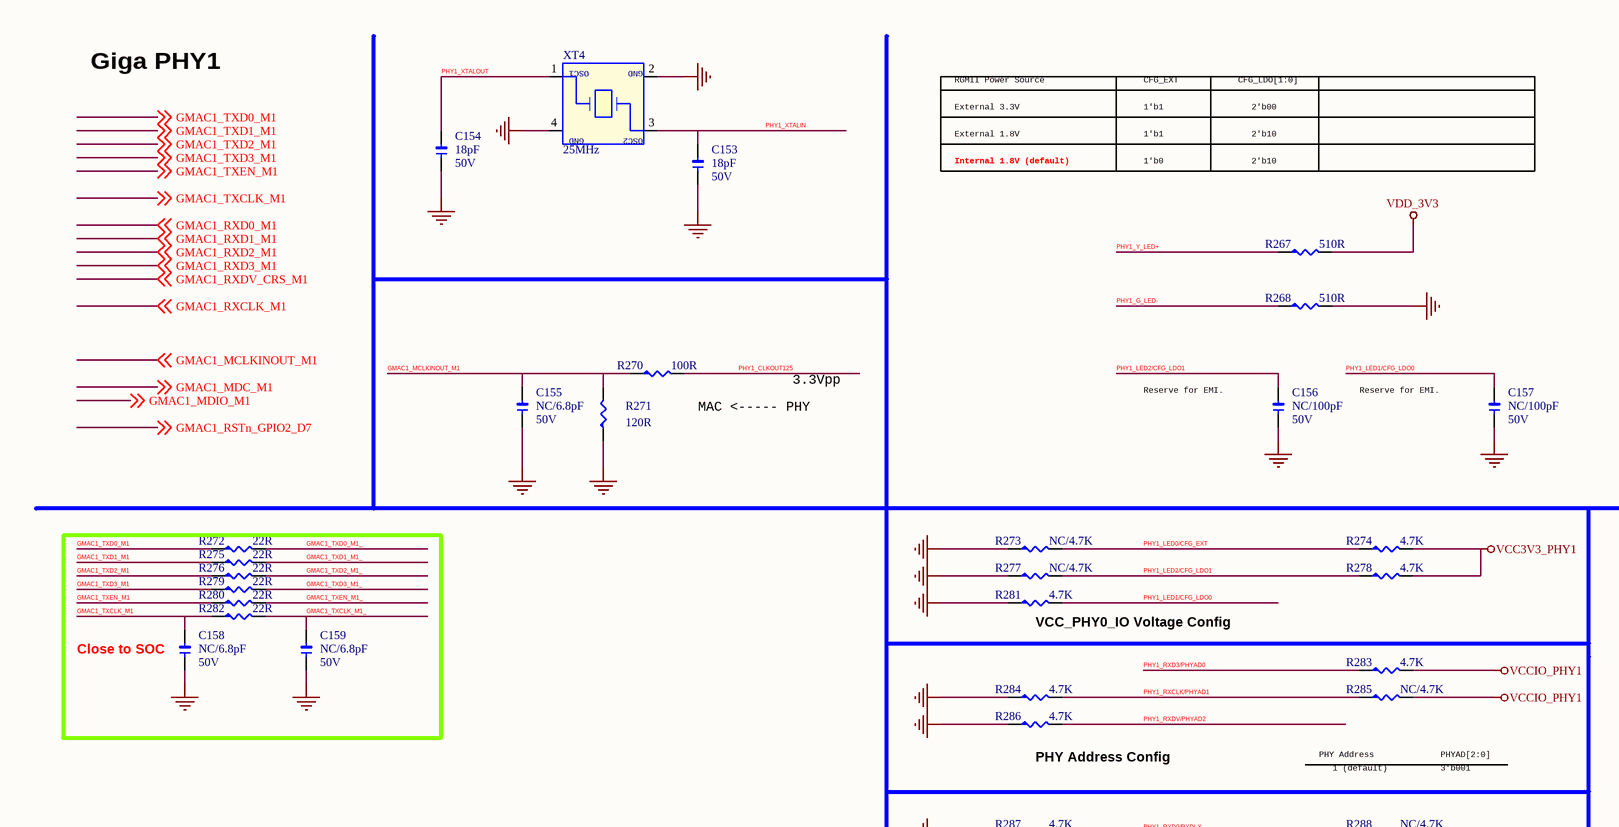
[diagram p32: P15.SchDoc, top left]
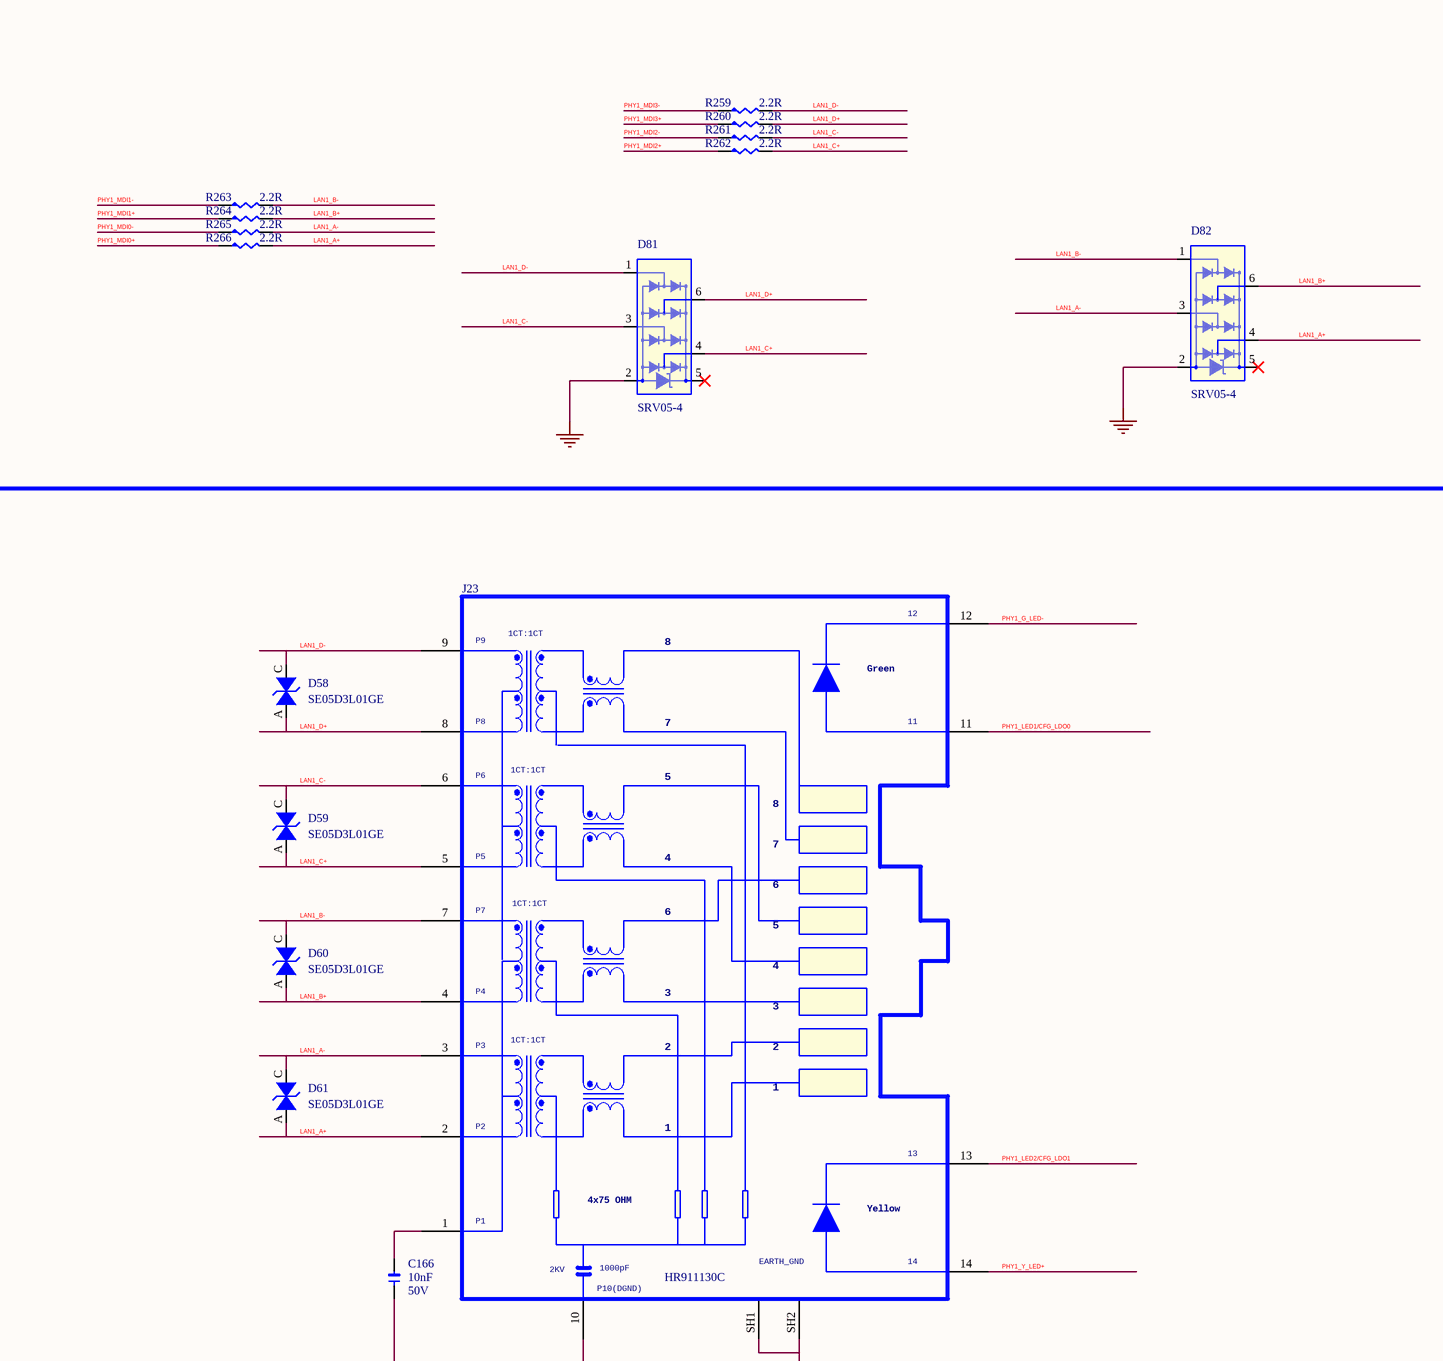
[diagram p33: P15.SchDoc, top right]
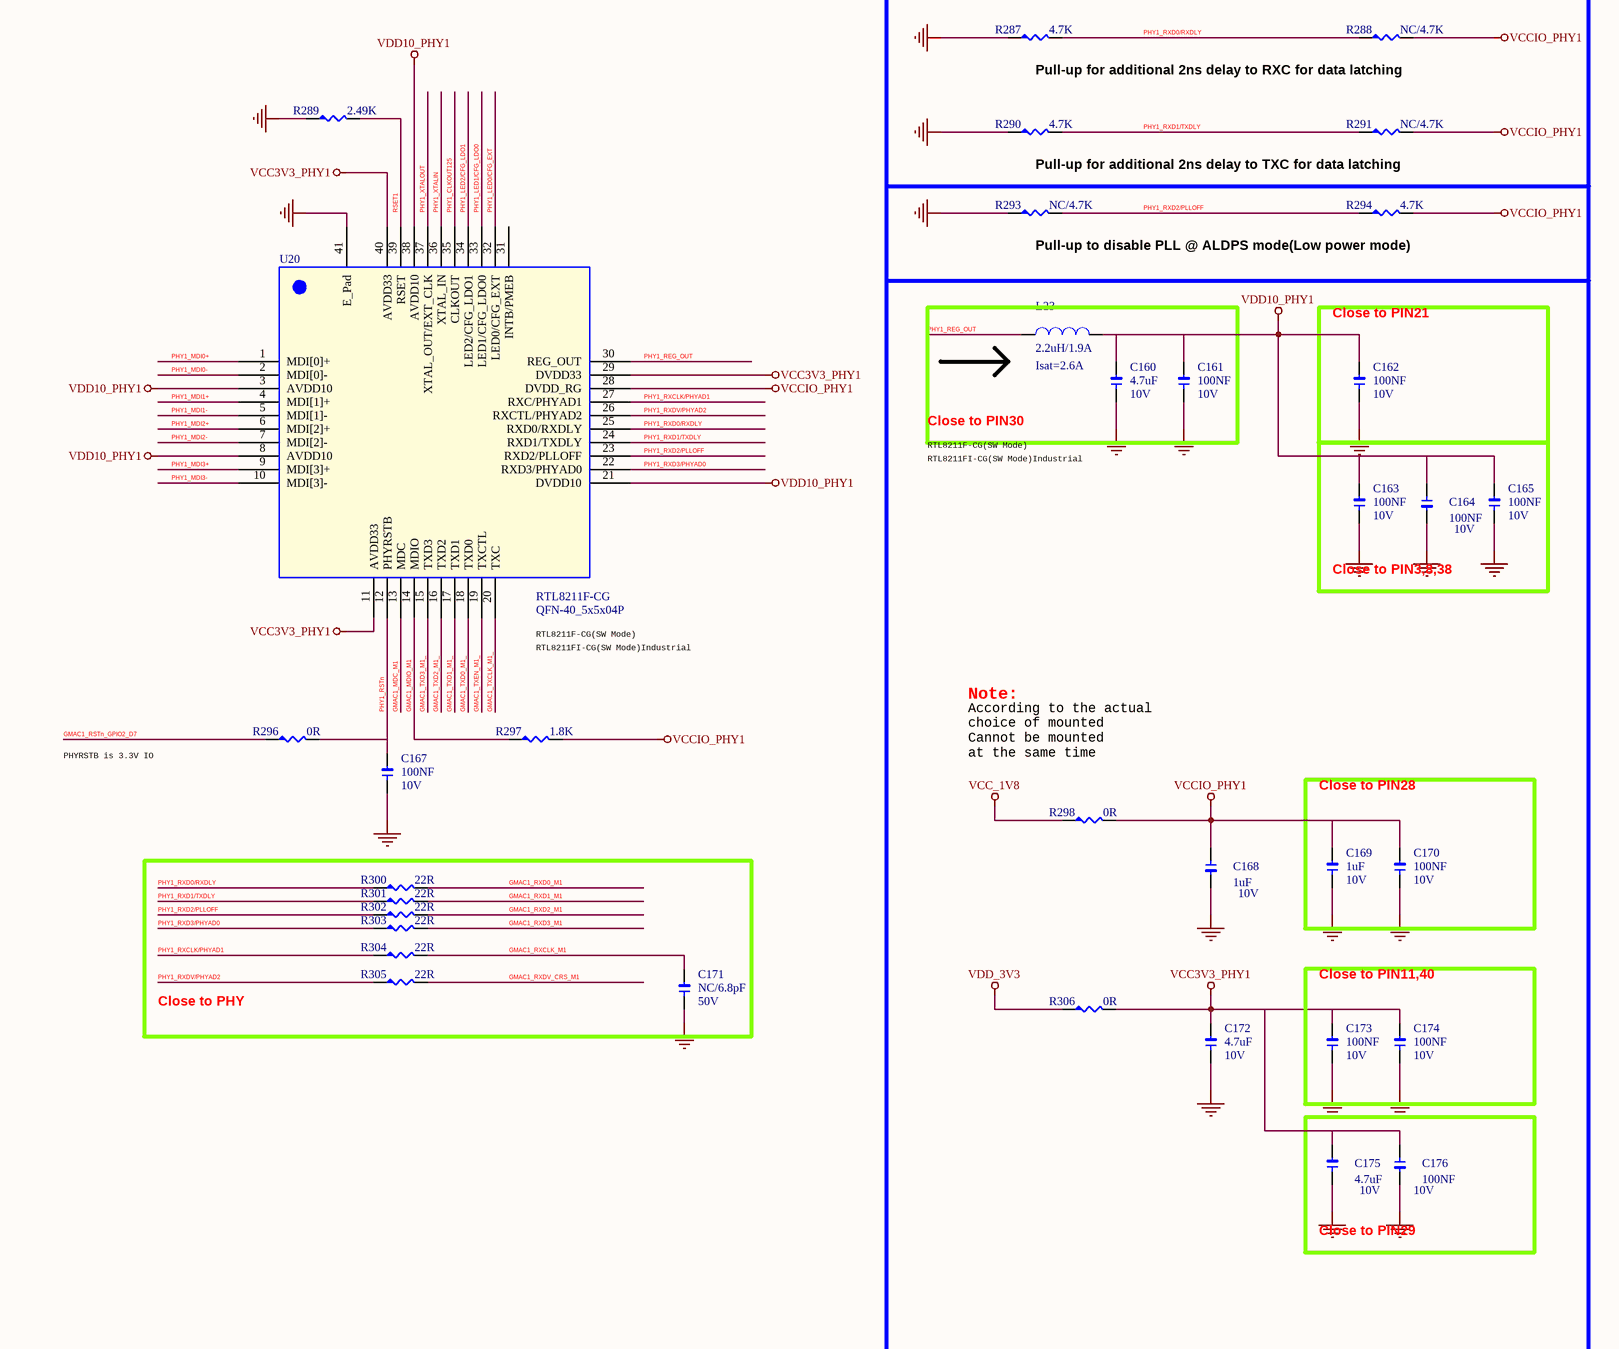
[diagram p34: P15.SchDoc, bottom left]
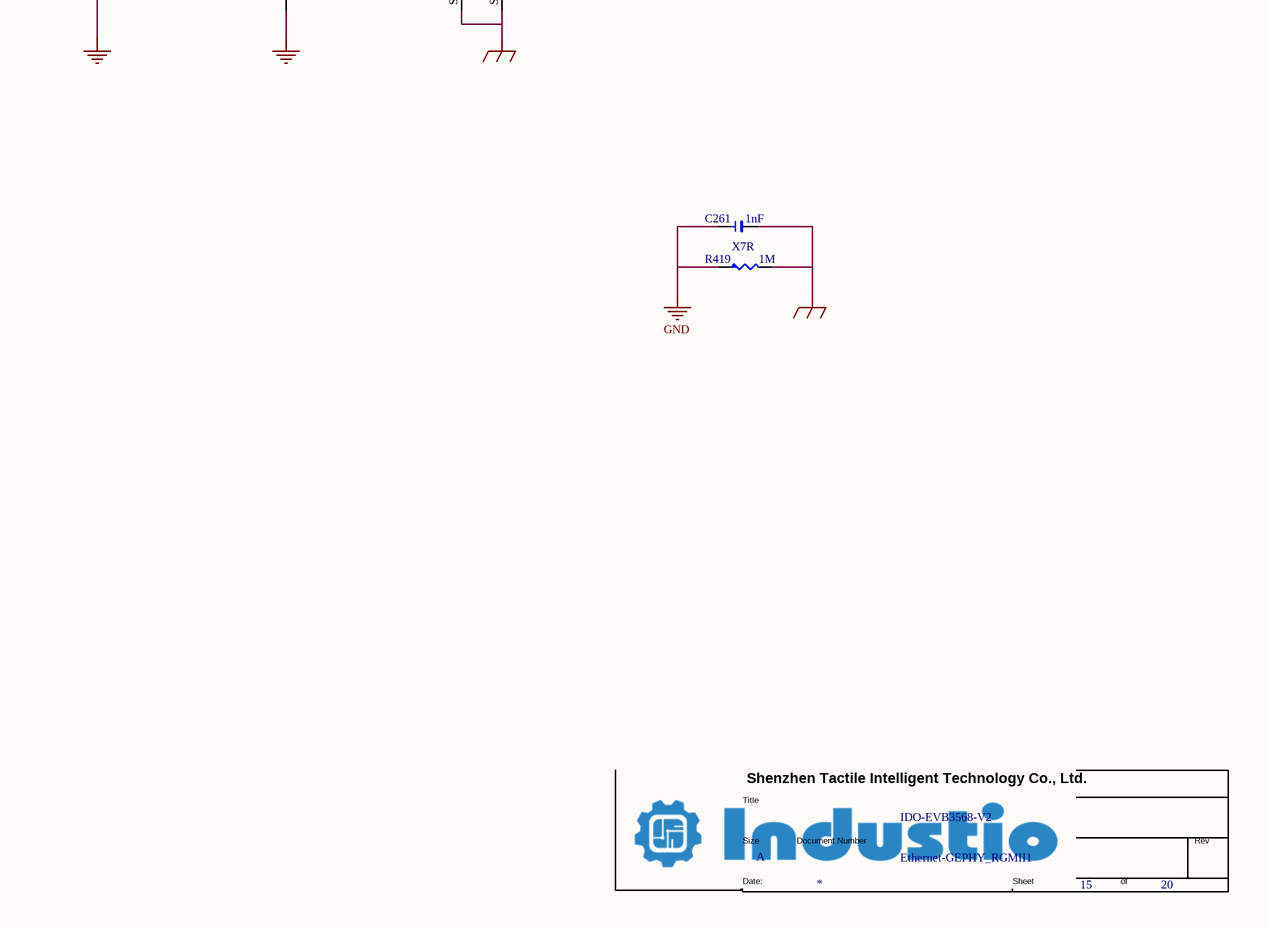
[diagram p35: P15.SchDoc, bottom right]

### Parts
(Parts that share a designator on the sheet are numbered #1, #2 ... from top to bottom, then left to right.)
*#14  Doc: Ethernet-GEPHY_RGMII1  Title: IDO-EVB3568-V2  Page Size: A  Page Number: 15  Page Count: 20  (hidden comment: TitleBlock1)  (graphical)
C153  18pF  DSC2: 50V  [1206]
C154  18pF  DSC2: 50V  [1206]
C155  NC/6.8pF  DSC2: 50V  [1206]
C156  NC/100pF  DSC2: 50V  [1206]
C157  NC/100pF  DSC2: 50V  [1206]
C158  NC/6.8pF  DSC2: 50V  [1206]
C159  NC/6.8pF  DSC2: 50V  [1206]
C160  4.7uF  DSC2: 10V  [1206]
C161  100NF  DSC2: 10V  [1206]
C162  100NF  DSC2: 10V  [1206]
C163  100NF  DSC2: 10V  [1206]
C164  100NF  DSC2: 10V  [1206]
C165  100NF  DSC2: 10V  [1206]
C166  10nF  DSC2: 50V  [1206]
C167  100NF  DSC2: 10V  [1206]
C168  1uF  DSC2: 10V  [1206]
C169  1uF  DSC2: 10V  [1206]
C170  100NF  DSC2: 10V  [1206]
C171  NC/6.8pF  DSC2: 50V  [1206]
C172  4.7uF  DSC2: 10V  [1206]
C173  100NF  DSC2: 10V  [1206]
C174  100NF  DSC2: 10V  [1206]
C175  4.7uF  DSC2: 10V  [1206]
C176  100NF  DSC2: 10V  [1206]
C261  1nF  DSC3: X7R  [1206]
D58  SE05D3L01GE  [SOD323]
D59  SE05D3L01GE  [SOD323]
D60  SE05D3L01GE  [SOD323]
D61  SE05D3L01GE  [SOD323]
D81  SRV05-4  [SOT23-6]
D82  SRV05-4  [SOT23-6]
J23  HR911130C  [RJ45-TH_HR911130A]
L23  2.2uH/1.9A  DSC2: Isat=2.6A  [IND_252012]
R259  2.2R  [R0402]
R260  2.2R  [R0402]
R261  2.2R  [R0402]
R262  2.2R  [R0402]
R263  2.2R  [R0402]
R264  2.2R  [R0402]
R265  2.2R  [R0402]
R266  2.2R  [R0402]
R267  510R  [R0402]
R268  510R  [R0402]
R270  100R  [R0402]
R271  120R  [R0402]
R272  22R  [R0402]
R273  NC/4.7K  [R0402]
R274  4.7K  [R0402]
R275  22R  [R0402]
R276  22R  [R0402]
R277  NC/4.7K  [R0402]
R278  4.7K  [R0402]
R279  22R  [R0402]
R280  22R  [R0402]
R281  4.7K  [R0402]
R282  22R  [R0402]
R283  4.7K  [R0402]
R284  4.7K  [R0402]
R285  NC/4.7K  [R0402]
R286  4.7K  [R0402]
R287  4.7K  [R0402]
R288  NC/4.7K  [R0402]
R289  2.49K  [R0402]
R290  4.7K  [R0402]
R291  NC/4.7K  [R0402]
R293  NC/4.7K  [R0402]
R294  4.7K  [R0402]
R296  0R  [R0402]
R297  1.8K  [R0402]
R298  0R  [R0402]
R300  22R  [R0402]
R301  22R  [R0402]
R302  22R  [R0402]
R303  22R  [R0402]
R304  22R  [R0402]
R305  22R  [R0402]
R306  0R  [R0402]
R419  1M  [R0805]
U20  RTL8211F-CG  PCB Footprint: QFN-40_5x5x04P  [QFN40_5R00X5R00X0R80_T]
XT4  25MHz  [xtal_32x25_4p]

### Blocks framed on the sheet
Close to SOC: C158 C159 R272 R275 R276 R279 R280 R282
Close to PIN30: C160 C161 L23
Close to PIN21: C162
Close to PIN3,8,38: C163-C165
Close to PIN28: C169 C170
Close to PHY: C171 R300-R305
Close to PIN11,40: C173 C174
Close to PIN29: C175 C176

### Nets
GND: C153.1 C154.1 C155.1 C156.1 C157.1 C158.1 C159.1 C160.1 C161.1 C162.1 C163.1 C164.2 C165.1 C166.1 C167.1 C168.2 C169.1 C170.1 C171.1 C172.1 C173.1 C174.1 C175.1 C176.2 C261.1 D81.2 D82.2 J23.10(GND) R268.2 R271.1 R273.1 R277.1 R281.1 R284.1 R286.1 R287.1 R289.1 R290.1 R293.1 R419.1 U20.41(E_Pad) XT4.2 XT4.4  [project net EDP_TX_AUXP_]
GND_EARTH: C261.2 J23.SH1 J23.SH2 R419.2
VCC3V3_PHY1: C172.2 C173.2 C174.2 C175.2 C176.1 R274.2 R278.2 R306.2 U20.11(AVDD33) U20.29(DVDD33) U20.40(AVDD33)
VCC_1V8: R298.1
VCCIO_PHY1: C168.1 C169.2 C170.2 R283.2 R285.2 R288.2 R291.2 R294.2 R297.2 R298.2 U20.28(DVDD_RG)
VDD10_PHY1: C160.2 C161.2 C162.2 C163.2 C164.1 C165.2 L23.2 U20.3(AVDD10) U20.8(AVDD10) U20.21(DVDD10) U20.38(AVDD10)
VDD_3V3: R267.2 R306.1
GMAC1_MCLKINOUT_M1: C155.2 R270.1 R271.2 ; off-sheet GMAC1_MCLKINOUT_M1
GMAC1_MDC_M1: U20.13(MDC) ; off-sheet GMAC1_MDC_M1
GMAC1_MDIO_M1: R297.1 U20.14(MDIO) ; off-sheet GMAC1_MDIO_M1
GMAC1_RSTn_GPIO2_D7: R296.1 ; off-sheet GMAC1_RSTn_GPIO2_D7
GMAC1_RXCLK_M1: C171.2 R304.2 ; off-sheet GMAC1_RXCLK_M1
GMAC1_RXD0_M1: R300.2 ; off-sheet GMAC1_RXD0_M1
GMAC1_RXD1_M1: R301.2 ; off-sheet GMAC1_RXD1_M1
GMAC1_RXD2_M1: R302.2 ; off-sheet GMAC1_RXD2_M1
GMAC1_RXD3_M1: R303.2 ; off-sheet GMAC1_RXD3_M1
GMAC1_RXDV_CRS_M1: R305.2 ; off-sheet GMAC1_RXDV_CRS_M1
GMAC1_TXCLK_M1: C158.2 R282.1 ; off-sheet GMAC1_TXCLK_M1
GMAC1_TXCLK_M1_: C159.2 R282.2 U20.20(TXC)
GMAC1_TXD0_M1: R272.1 ; off-sheet GMAC1_TXD0_M1
GMAC1_TXD0_M1_: R272.2 U20.18(TXD0)
GMAC1_TXD1_M1: R275.1 ; off-sheet GMAC1_TXD1_M1
GMAC1_TXD1_M1_: R275.2 U20.17(TXD1)
GMAC1_TXD2_M1: R276.1 ; off-sheet GMAC1_TXD2_M1
GMAC1_TXD2_M1_: R276.2 U20.16(TXD2)
GMAC1_TXD3_M1: R279.1 ; off-sheet GMAC1_TXD3_M1
GMAC1_TXD3_M1_: R279.2 U20.15(TXD3)
GMAC1_TXEN_M1: R280.1 ; off-sheet GMAC1_TXEN_M1
GMAC1_TXEN_M1_: R280.2 U20.19(TXCTL)
LAN1_A+: D61.A(I/O2) D82.4 J23.2(MDI_0+) R266.2
LAN1_A-: D61.C(I/O1) D82.3 J23.3(MDI_0-) R265.2
LAN1_B+: D60.A(I/O2) D82.6 J23.4(MDI_1+) R264.2
LAN1_B-: D60.C(I/O1) D82.1 J23.7(MDI_1-) R263.2
LAN1_C+: D59.A(I/O2) D81.4 J23.5(MDI_2+) R262.2
LAN1_C-: D59.C(I/O1) D81.3 J23.6(MDI_2-) R261.2
LAN1_D+: D58.A(I/O2) D81.6 J23.8(MDI_3+) R260.2
LAN1_D-: D58.C(I/O1) D81.1 J23.9(MDI_3-) R259.2
PHY1_CLKOUT125: R270.2 U20.35(CLKOUT)
PHY1_G_LED-: J23.12(G_LED-) R268.1
PHY1_LED0/CFG_EXT: R273.2 R274.1 U20.32(LED0/CFG_EXT)
PHY1_LED1/CFG_LDO0: C157.2 J23.11(G_LED+) R281.2 U20.33(LED1/CFG_LDO0)
PHY1_LED2/CFG_LDO1: C156.2 J23.13(Y_LED-) R277.2 R278.1 U20.34(LED2/CFG_LDO1)
PHY1_MDI0+: R266.1 U20.1(MDI[0]+)
PHY1_MDI0-: R265.1 U20.2(MDI[0]-)
PHY1_MDI1+: R264.1 U20.4(MDI[1]+)
PHY1_MDI1-: R263.1 U20.5(MDI[1]-)
PHY1_MDI2+: R262.1 U20.6(MDI[2]+)
PHY1_MDI2-: R261.1 U20.7(MDI[2]-)
PHY1_MDI3+: R260.1 U20.9(MDI[3]+)
PHY1_MDI3-: R259.1 U20.10(MDI[3]-)
PHY1_REG_OUT: L23.1 U20.30(REG_OUT)
PHY1_RSTn: C167.2 R296.2 U20.12(PHYRSTB)
PHY1_RXCLK/PHYAD1: R284.2 R285.1 R304.1 U20.27(RXC/PHYAD1)
PHY1_RXD0/RXDLY: R287.2 R288.1 R300.1 U20.25(RXD0/RXDLY)
PHY1_RXD1/TXDLY: R290.2 R291.1 R301.1 U20.24(RXD1/TXDLY)
PHY1_RXD2/PLLOFF: R293.2 R294.1 R302.1 U20.23(RXD2/PLLOFF)
PHY1_RXD3/PHYAD0: R283.1 R303.1 U20.22(RXD3/PHYAD0)
PHY1_RXDV/PHYAD2: R286.2 R305.1 U20.26(RXCTL/PHYAD2)
PHY1_XTALIN: C153.2 U20.36(XTAL_IN) XT4.3
PHY1_XTALOUT: C154.2 U20.37(XTAL_OUT/EXT_CLK) XT4.1
PHY1_Y_LED+: J23.14(Y_LED+) R267.1
RSET1: R289.2 U20.39(RSET)
NetC166_2: C166.2 J23.1(CT1/2/3/4)

Not connected (* = marked no-connect by the designer): D81 5*; D82 5*; U20 31(INTB/PMEB)

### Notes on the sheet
- Giga PHY1
- RGMII Power Source
- External 3.3V
- CFG_EXT
- 1'b1
- CFG_LDO[1:0]
- 2'b00
- External 1.8V
- Internal 1.8V (default)
- 1'b0
- 2'b10
- 3.3Vpp
- (near R270) MAC <----- PHY
- Reserve for EMI.
- (near R281) VCC_PHY0_IO Voltage Config
- (near R286) PHY Address Config
- PHY Address
- 1 (default)
- PHYAD[2:0]
- 3'b001
- Pull-up for additional 2ns delay to RXC for data latching
- Pull-up for additional 2ns delay to TXC for data latching
- Pull-up to disable PLL @ ALDPS mode(Low power mode)
- RTL8211F-CG(SW Mode)
- RTL8211FI-CG(SW Mode)Industrial
- Note:
- (near R298) According to the actual
  choice of mounted
  Cannot be mounted
  at the same time
- PHYRSTB is 3.3V IO

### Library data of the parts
C153 C154 = C-0402_Dup2: as C114 on sheet P13
C155 C171 = C-0402_Dup2: Part Number: C020102120018; Part Name: 贴片电容; Manufacture: 三星¦国巨¦村田; PCB Footprint: C0402; ERP Number: 1010200056; DSC1: ±0.25PF; DSC3: C0G; ID: 18
C156 = C-0402_Dup2: Part Number: C020102120040; Part Name: 贴片电容; Manufacture: 三星¦国巨¦村田; PCB Footprint: C0402; ERP Number: 1010200152; DSC1: ±5%; DSC3: C0G; ID: 40
C157 = C-0402_Dup2: Manufacture: 三星¦国巨¦村田; Part Name: 贴片电容; Part Number: C020102120040; PCB Footprint: C0402; ID: 40; DSC3: C0G; DSC1: ±5%; ERP Number: 1010200152
C158 C159 = C-0402_Dup2: Manufacture: 三星¦国巨¦村田; Part Name: 贴片电容; Part Number: C020102120018; PCB Footprint: C0402; ID: 18; DSC3: C0G; DSC1: ±0.25PF; ERP Number: 1010200056
C160 C175 = C-0402_Dup2: Part Number: C020102120067; Part Name: 贴片电容; Manufacture: 三星¦国巨¦村田; PCB Footprint: C0402; DSC1: ±20%; DSC3: X5R; ID: 67
C161-C163 C165 C167 C176 = C-0402_Dup2: Manufacture: 三星¦国巨¦村田; Part Name: 贴片电容; Part Number: C020102120060; PCB Footprint: C0402; ID: 60; DSC3: X7R; DSC1: ±10%
C164 C170 C173 C174 = C-0402_Dup2: Part Number: C020102120060; Part Name: 贴片电容; Manufacture: 三星¦国巨¦村田; PCB Footprint: C0402; DSC1: ±10%; DSC3: X7R; ID: 60
C166 = C-0402_Dup2: Manufacture: 三星¦国巨¦村田; Part Name: 贴片电容; Part Number: C020102120057; PCB Footprint: C0402; ID: 57; DSC3: X7R; DSC1: ±10%; ERP Number: 1010200077
C168 = C-0402_Dup2: Part Number: C020102120064; Part Name: 贴片电容; Manufacture: 三星¦国巨¦村田; PCB Footprint: C0402; ERP Number: 1010200054; DSC1: ±10%; DSC3: X5R; ID: 64
C169 = C-0402_Dup2: Manufacture: 三星¦国巨¦村田; Part Name: 贴片电容; Part Number: C020102120064; PCB Footprint: C0402; ID: 64; DSC3: X5R; DSC1: ±10%; ERP Number: 1010200054
C172 = C-0402_Dup2: Manufacture: 三星¦国巨¦村田; Part Name: 贴片电容; Part Number: C020102120067; PCB Footprint: C0402; ID: 67; DSC3: X5R; DSC1: ±20%
C261 = C-1206: Manufacture: 三星¦国巨¦村田; Part Name: 贴片电容; Part Number: C020102120077; DSC2: 2KV; DSC1: ±10%; ERP Number: 1010200094; PCB Footprint: C1206
D58 D61 = DI-TVS-D: as D55 on sheet P14
D59 D60 = DI-TVS-D: as D54 on sheet P14
D81 = DI-ESD-SRV05-4: as D84 on sheet P14
D82 = DI-ESD-SRV05-4: as D83 on sheet P14
J23 = J-RJ45-HR911130C: Part Number: J120103060005; Part Name: RJ45; DSC1: RJ45 8P插件 内置千兆变压器(商业级)  双灯 卧式 全包带弹片,16x21.3x13.5mm; DSC2: 通孔弯针; DSC4: HR911130C(汉仁); ID: 5
L23 = L-IND: Part Name: 功率电感; Manufacture: 宗成¦长江微电¦顺络; DSC1: ±20%; DSC3: Irms=1.9A; DSC4: 120mΩ; DSC5: 2.5*2.0*1.2mm; DSC6: WPN252012H2R2MT(顺络); DSC7: FHD252012S-2R2MT(长江微电); DSC8: ZCRH252012-2.2uH-M(宗成); ID: 53
R259-R266 = R-0402_Dup4: Part Number: C011002080238; Part Name: 贴片电阻; ID: 238; DSC2: 1/16W; DSC1: ±5%; ERP Number: 1010200263
R267 R268 = R-0402_Dup4: Part Number: C011002080296; Part Name: 贴片电阻; ID: 296; DSC2: 1/16W; DSC1: ±5%; ERP Number: 1010200226
R270 = R-0402_Dup4: Part Name: 贴片电阻; Part Number: C011002080279; ERP Number: 1010200160; DSC1: ±5%; DSC2: 1/16W; ID: 279
R271 = R-0402_Dup4: Part Name: 贴片电阻; Part Number: C011002080281; DSC1: ±5%; DSC2: 1/16W; ID: 281
R272 R275 R276 R279 R280 R282 R300-R305 = R-0402_Dup4: as R181-R184 on sheet P13
R273 R277 R285 R288 R291 R293 = R-0402_Dup4: as R226 on sheet P14
R274 R278 R281 R283 R284 R286 R287 R290 R294 = R-0402_Dup4: as R225 on sheet P14
R289 = R-0402_Dup5: Part Number: C011002080785; Part Name: 贴片电阻; ID: 785; DSC2: 1/16W; DSC1: ±1%; ERP Number: 1010200324
R296 R306 = R-0402_Dup4: as R191 on sheet P13
R297 = R-0402_Dup4: Part Name: 贴片电阻; Part Number: C011002080309; DSC1: ±5%; DSC2: 1/16W; ID: 309
R298 = R-0402_Dup4: as R205 on sheet P13
R419 = R-0805: Part Number: C011002081864; Part Name: 贴片电阻; DSC2: 1/8W; DSC1: ±1%; ERP Number: 1010200447
U20 = Ethernet_RTL8211F: as U19 on sheet P14
XT4 = XTAL-4P_Dup1: Part Name: 贴片无源晶振; Part Number: C050102290006; Manufacture: 泰晶; CLASS: IC; DSC1: 40Ω; DSC2: ±10ppm; DSC3: 12pF; DSC4: -40℃~+85℃; DSC5: 3.2*2.5mm 4P; ID: 6

## Sheet P16.SchDoc
size 420 x 297 mm
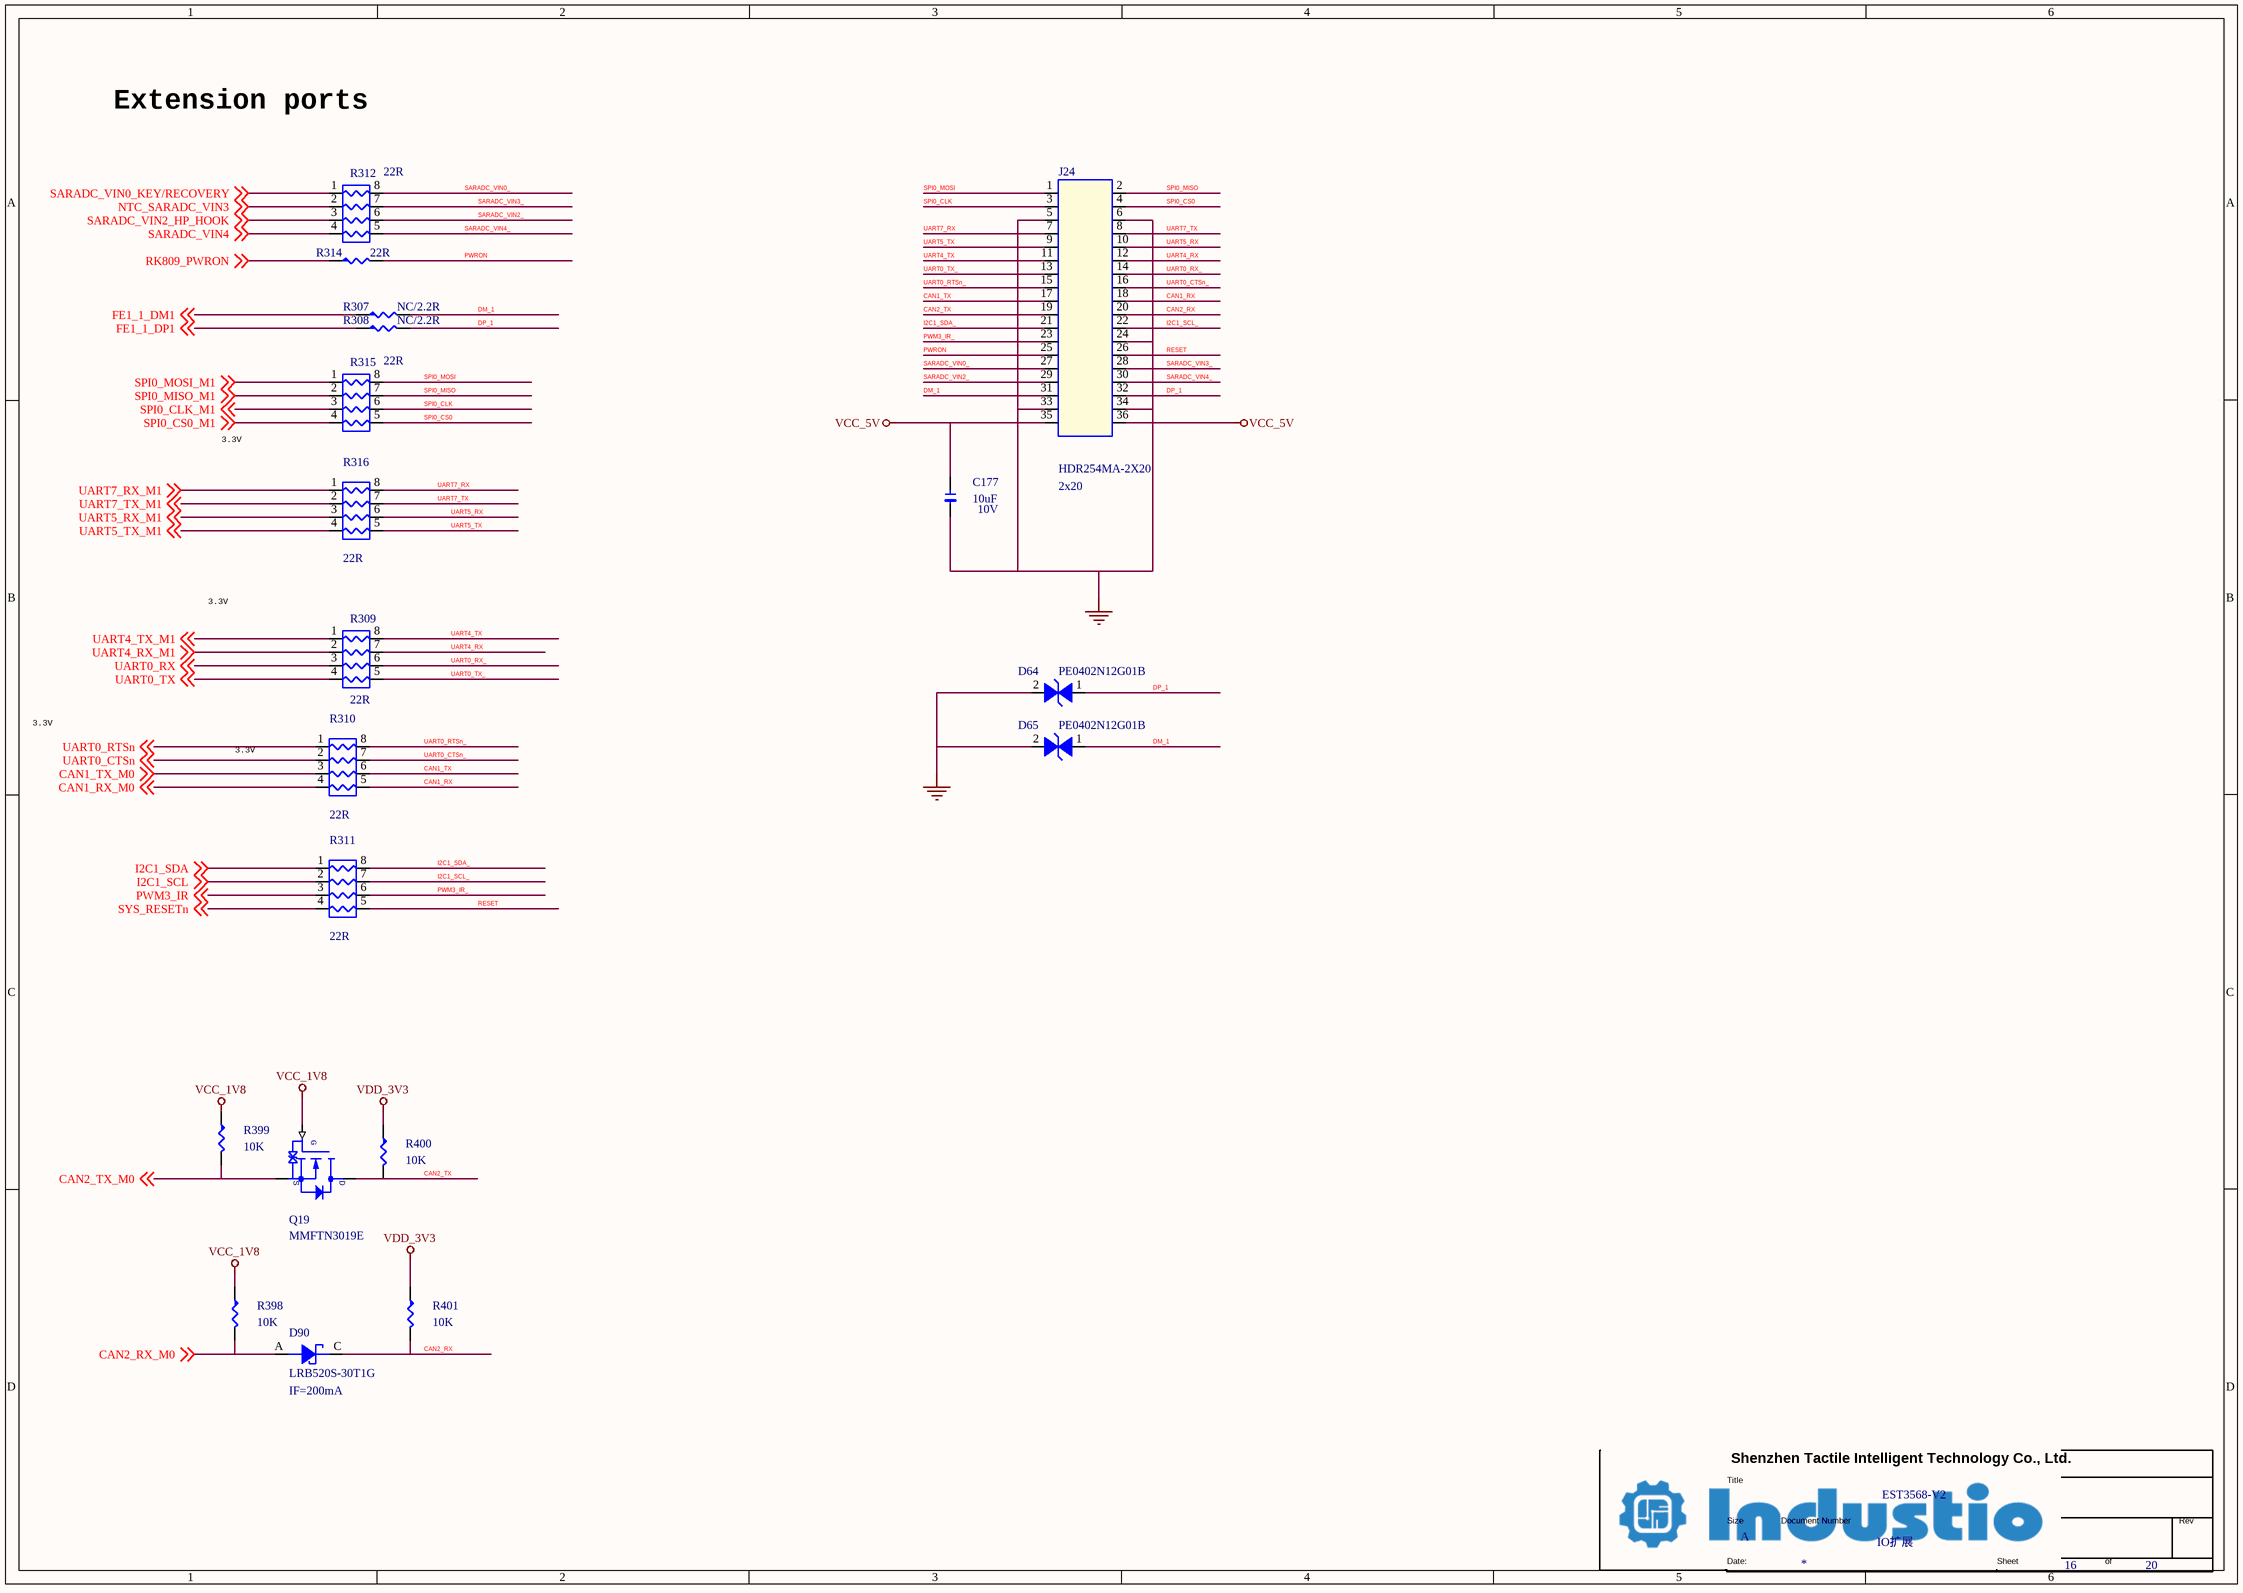
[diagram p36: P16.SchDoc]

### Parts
(Parts that share a designator on the sheet are numbered #1, #2 ... from top to bottom, then left to right.)
*#15  Doc: IO扩展  Title: EST3568-V2  Page Size: A  Page Number: 16  Page Count: 20  (hidden comment: TitleBlock1)  (graphical)
C177  10uF  DSC2: 10V  [1206]
D64  PE0402N12G01B  [V0402]
D65  PE0402N12G01B  [V0402]
D90  LRB520S-30T1G  DSC2: IF=200mA  [SOD523]
J24  HDR254MA-2X20  DSC2: 2x20  [HDR254MA-2X18]
Q19  MMFTN3019E  [SOT523]
R307  NC/2.2R  [R0402]
R308  NC/2.2R  [R0402]
R309  22R  [RN_0402X4]
R310  22R  [RN_0402X4]
R311  22R  [RN_0402X4]
R312  22R  [RN_0402X4]
R314  22R  [R0402]
R315  22R  [RN_0402X4]
R316  22R  [RN_0402X4]
R398  10K  [R0402]
R399  10K  [R0402]
R400  10K  [R0402]
R401  10K  [R0402]

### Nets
GND: C177.2 D64.2(I/O1) D65.2(I/O1) J24.5 J24.6 J24.24 J24.33 J24.34  [project net EDP_TX_AUXP_]
VCC_1V8: Q19.1(GATE) R398.1 R399.1
VCC_5V: C177.1 J24.35 J24.36
VDD_3V3: R400.1 R401.1
CAN1_RX: J24.18 R310.5
CAN1_RX_M0: R310.4 ; off-sheet CAN1_RX_M0
CAN1_TX: J24.17 R310.6
CAN1_TX_M0: R310.3 ; off-sheet CAN1_TX_M0
CAN2_RX: D90.C J24.20 R401.2
CAN2_RX_M0: D90.A R398.2 ; off-sheet CAN2_RX_M0
CAN2_TX: J24.19 Q19.3(DRAIN) R400.2
CAN2_TX_M0: Q19.2(SOURCE) R399.2 ; off-sheet CAN2_TX_M0
DM_1: D65.1(I/O2) J24.31 R307.2
DP_1: D64.1(I/O2) J24.32 R308.2
FE1_1_DM1: R307.1 ; off-sheet FE1_1_DM1
FE1_1_DP1: R308.1 ; off-sheet FE1_1_DP1
I2C1_SCL: R311.2 ; off-sheet I2C1_SCL
I2C1_SCL_: J24.22 R311.7
I2C1_SDA: R311.1 ; off-sheet I2C1_SDA
I2C1_SDA_: J24.21 R311.8
NTC_SARADC_VIN3: R312.2 ; off-sheet NTC_SARADC_VIN3
PWM3_IR: R311.3 ; off-sheet PWM3_IR
PWM3_IR_: J24.23 R311.6
PWRON: J24.25 R314.2
RESET: J24.26 R311.5
RK809_PWRON: R314.1 ; off-sheet RK809_PWRON
SARADC_VIN0_: J24.27 R312.8
SARADC_VIN0_KEY/RECOVERY: R312.1 ; off-sheet SARADC_VIN0_KEY/RECOVERY
SARADC_VIN2_: J24.29 R312.6
SARADC_VIN2_HP_HOOK: R312.3 ; off-sheet SARADC_VIN2_HP_HOOK
SARADC_VIN3_: J24.28 R312.7
SARADC_VIN4: R312.4 ; off-sheet SARADC_VIN4
SARADC_VIN4_: J24.30 R312.5
SPI0_CLK: J24.3 R315.6
SPI0_CLK_M1: R315.3 ; off-sheet SPI0_CLK_M1
SPI0_CS0: J24.4 R315.5
SPI0_CS0_M1: R315.4 ; off-sheet SPI0_CS0_M1
SPI0_MISO: J24.2 R315.7
SPI0_MISO_M1: R315.2 ; off-sheet SPI0_MISO_M1
SPI0_MOSI: J24.1 R315.8
SPI0_MOSI_M1: R315.1 ; off-sheet SPI0_MOSI_M1
SYS_RESETn: R311.4 ; off-sheet SYS_RESETn
UART0_CTSn: R310.2 ; off-sheet UART0_CTSn
UART0_CTSn_: J24.16 R310.7
UART0_RTSn: R310.1 ; off-sheet UART0_RTSn
UART0_RTSn_: J24.15 R310.8
UART0_RX: R309.3 ; off-sheet UART0_RX
UART0_RX_: J24.14 R309.6
UART0_TX: R309.4 ; off-sheet UART0_TX
UART0_TX_: J24.13 R309.5
UART4_RX: J24.12 R309.7
UART4_RX_M1: R309.2 ; off-sheet UART4_RX_M1
UART4_TX: J24.11 R309.8
UART4_TX_M1: R309.1 ; off-sheet UART4_TX_M1
UART5_RX: J24.10 R316.6
UART5_RX_M1: R316.3 ; off-sheet UART5_RX_M1
UART5_TX: J24.9 R316.5
UART5_TX_M1: R316.4 ; off-sheet UART5_TX_M1
UART7_RX: J24.7 R316.8
UART7_RX_M1: R316.1 ; off-sheet UART7_RX_M1
UART7_TX: J24.8 R316.7
UART7_TX_M1: R316.2 ; off-sheet UART7_TX_M1

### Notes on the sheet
- Extension ports
- 3.3V

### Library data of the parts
C177 = C-0603_Dup1: Part Number: C020102120071; Part Name: 贴片电容; Manufacture: 三星¦国巨¦村田; ERP Number: 1010200076; DSC1: ±20%; DSC3: X5R; ID: 71; PCB Footprint: C0603
D64 D65 = DI-ESD: ESD 0402; Manufacturer: INPAQ; Manufacture P/N: MLVG04021R0UV18; Part Number: C040504013980; Manufacture: 硕凯; PN Type: Varistor; Solder: 推荐; ID: 1; DSC5: Cj=0.05pF; DSC4: Vc=40V; DSC2: Vdc=12V; DSC1: 双向
D90 = DI-XI-S: Manufacture: 乐山无线电; Part Name: 肖特基二级管; Part Number: C040202220002; CLASS: IC; Solder: 推荐; ID: 2; DSC4: IR=0.5uA; DSC3: VF=350mV/10mA; DSC1: VR=30V
J24 = J-HDR-D-40_0: Part Name: 双排针; Part Number: J010104013835; ID: 64; DSC7: A2541WV-2x20P(CJT); DSC6: 黑胶; DSC5: 针长11.5mm 3+2.5(H塑高)+6mm; DSC4: 通孔直针; DSC3: 2.54mm脚距; DSC1: 双排单塑
Q19 = N-MOS-Q_Dup1: Manufacture: 先科; Part Name: N-MOS; Part Number: C030202190004; ID: 4; DSC5: pd=150mW; DSC4: Vgs=±20V; DSC3: Vgs(th)=1.5V; DSC2: Id=100mA; DSC1: Vds=30V; ERP Number: 1010800011
R307 R308 = R-0402_Dup4: as R214 on sheet P14
R309 R315 R316 = RN_0402X4: Part Name: 贴片排阻; Part Number: C010302090004; ID: 4; DSC1: ±5%; DSC2: 1/16W
R310-R312 = RN_0402X4: Part Number: C010302090004; Part Name: 贴片排阻; DSC2: 1/16W; DSC1: ±5%; ID: 4
R314 = R-0402_Dup4: as R224 on sheet P14
R398 = R-0402_Dup4: Part Number: C011002080328; Part Name: 贴片电阻; ID: 328; DSC2: 1/16W; DSC1: ±5%; ERP Number: 1010200096
R399-R401 = R-0402_Dup4: as R180 on sheet P13

## Sheet P17.SchDoc
size 297 x 209 mm
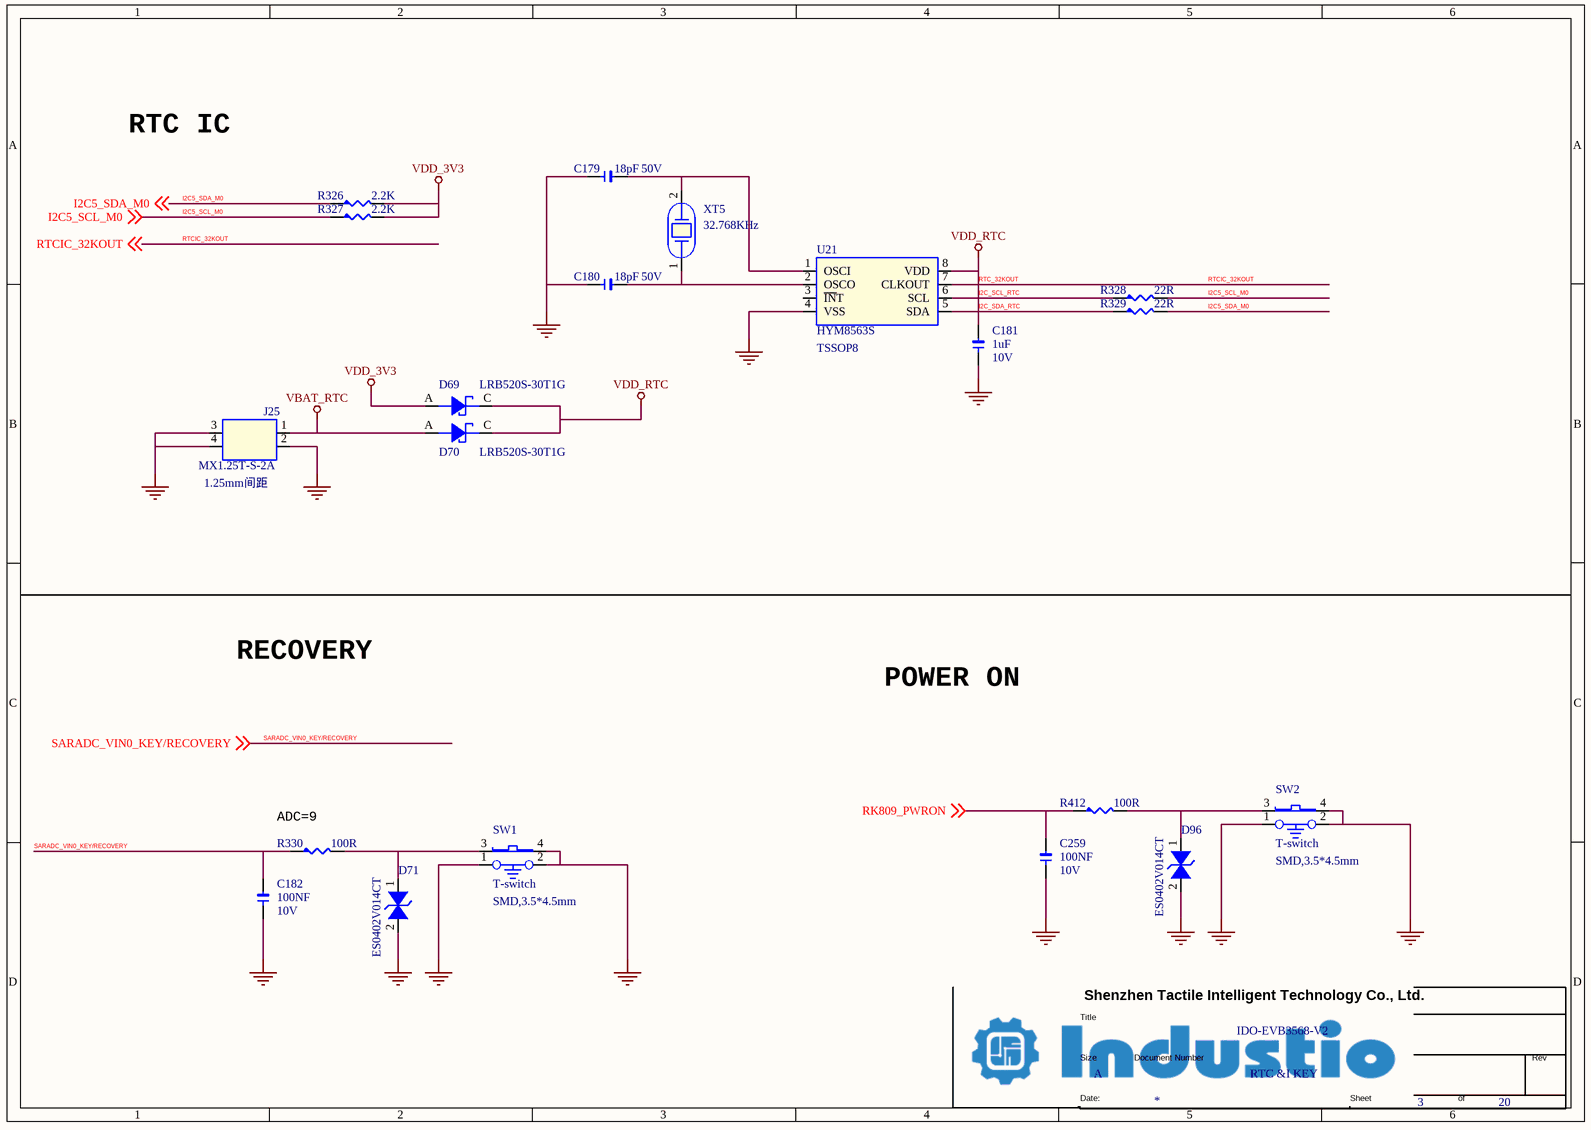
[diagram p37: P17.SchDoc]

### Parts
(Parts that share a designator on the sheet are numbered #1, #2 ... from top to bottom, then left to right.)
*#16  Doc: RTC &I KEY  Title: IDO-EVB3568-V2  Page Size: A  Page Number: 3  Page Count: 20  (hidden comment: TitleBlock1)  (graphical)
C179  18pF  DSC2: 50V  [1206]
C180  18pF  DSC2: 50V  [1206]
C181  1uF  DSC2: 10V  [1206]
C182  100NF  DSC2: 10V  [1206]
C259  100NF  DSC2: 10V  [1206]
D69  LRB520S-30T1G  [SOD523]
D70  LRB520S-30T1G  [SOD523]
D71  ES0402V014CT  [V0402]
D96  ES0402V014CT  [V0402]
J25  MX1.25T-S-2A  DSC2: 1.25mm间距  [MX125T-S-2A]
R326  2.2K  [R0402]
R327  2.2K  [R0402]
R328  22R  [R0402]
R329  22R  [R0402]
R330  100R  [R0402]
R412  100R  [R0402]
SW1  T-switch  DSC2: SMD,3.5*4.5mm  [PB-SIDE-S-3_5x4_5]
SW2  T-switch  DSC2: SMD,3.5*4.5mm  [PB-SIDE-S-3_5x4_5]
U21  HYM8563S  DSC2: TSSOP8  [TSSOP-8]
XT5  32.768KHz  [XTAL_32X15_2P]

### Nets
GND: C179.1 C180.1 C181.1 C182.1 C259.1 D71.2(I/O1) D96.2(I/O1) J25.2 J25.3 J25.4 SW1.1 SW1.2 SW1.4 SW2.1 SW2.2 SW2.4 U21.4(VSS)  [project net EDP_TX_AUXP_]
I2C_SCL_RTC: C181.2 D69.C D70.C R328.1 R329.1 U21.5(SDA) U21.6(SCL) U21.7(CLKOUT) U21.8(VDD) ; off-sheet RTCIC_32KOUT  [also labelled I2C_SDA_RTC, RTC_32KOUT, RTCIC_32KOUT, VDD_RTC]
VBAT_RTC: D70.A J25.1
VDD_3V3: D69.A R326.2 R327.2
I2C5_SCL_M0: R327.1 R328.2 ; off-sheet I2C5_SCL_M0
I2C5_SDA_M0: R326.1 R329.2 ; off-sheet I2C5_SDA_M0
RK809_PWRON: C259.2 R412.1 ; off-sheet RK809_PWRON
SARADC_VIN0_KEY/RECOVERY: C182.2 R330.1 ; off-sheet SARADC_VIN0_KEY/RECOVERY
NetC179_2: C179.2 U21.1(OSCI) XT5.2
NetC180_2: C180.2 U21.2(OSCO) XT5.1
NetD71_1: D71.1(I/O2) R330.2 SW1.3
NetD96_1: D96.1(I/O2) R412.2 SW2.3

Not connected (* = marked no-connect by the designer): U21 3(~{IN}T)

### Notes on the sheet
- RTC IC
- RECOVERY
- POWER ON
- (near R330) ADC=9

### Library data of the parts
C179 C180 = C-0402_Dup2: Manufacture: 三星¦国巨¦村田; Part Name: 贴片电容; Part Number: C020102120027; ID: 27; DSC3: C0G; DSC1: ±5%; ERP Number: 1010200091; PCB Footprint: C0402
C181 = C-0402_Dup2: as C168 on sheet P15
C182 C259 = C-0402_Dup2: as C122 on sheet P13
D69 D70 = DI-XI-S: Manufacture: 乐山无线电; Part Name: 肖特基二级管; Part Number: C040202220002; CLASS: IC; Solder: 推荐; ID: 2; DSC4: IR=0.5uA; DSC3: VF=350mV/10mA; DSC2: IF=200mA; DSC1: VR=30V
D71 D96 = DI-ESD_Dup1: ESD 0402; Manufacturer: INPAQ; Manufacture P/N: MLVG04021R0UV18; Part Number: C040502250002; Manufacture: AEM; PN Type: Varistor; ID: 2; DSC5: Cj=0.25pF; DSC4: Vc=30V; DSC3: Vbr=300V; DSC2: Vdc=14V; DSC1: 双向; ERP Number: 1010800023
J25 = J-A-2P: Part Number: J020102800058; DSC1: 2p; DSC3: 立贴; DSC4: 米黄色胶壳 耐高温; DSC5: JLX-1.25T-2AB(九龙熹); DSC6: X9821WVS-02-9TSN(星坤); ID: 6
R326 = R-0402_Dup4: Part Name: 贴片电阻; Part Number: C011002080311; ERP Number: 1010200170; DSC1: ±5%; DSC2: 1/16W; ID: 311
R327 = R-0402_Dup4: Part Number: C011002080311; Part Name: 贴片电阻; ID: 311; DSC2: 1/16W; DSC1: ±5%; ERP Number: 1010200170
R328 = R-0402_Dup4: as R224 on sheet P14
R329 = R-0402_Dup4: as R181-R184 on sheet P13
R330 R412 = R-0402_Dup4: as R216 on sheet P14
SW1 SW2 = SW-TS24CA: Part Number: C180102690004; Part Name: 轻触开关; DSC1: 轻触开关 侧键 贴片 带定位柱; DSC3: TS24CA(首韩); ID: 4
U21 = U-HYM8563S: Manufacture: HAOYU(昊昱); Part Name: RTC芯片; Part Number: C110204273853; ID: 16; DSC3: -40℃~+85℃; DSC1: RTC,I2C, VCC=2.0-5.5V
XT5 = XTAL-2P: Part Name: 贴片无源晶振; Part Number: C050102290002; Manufacture: 泰晶; CLASS: IC; DSC1: 70kΩ; DSC2: ±20ppm; DSC3: 12.5pF; DSC4: -40℃~+85℃; DSC5: 3.2*1.5mm 2P; ID: 2

## Sheet P18.SchDoc
size 420 x 297 mm
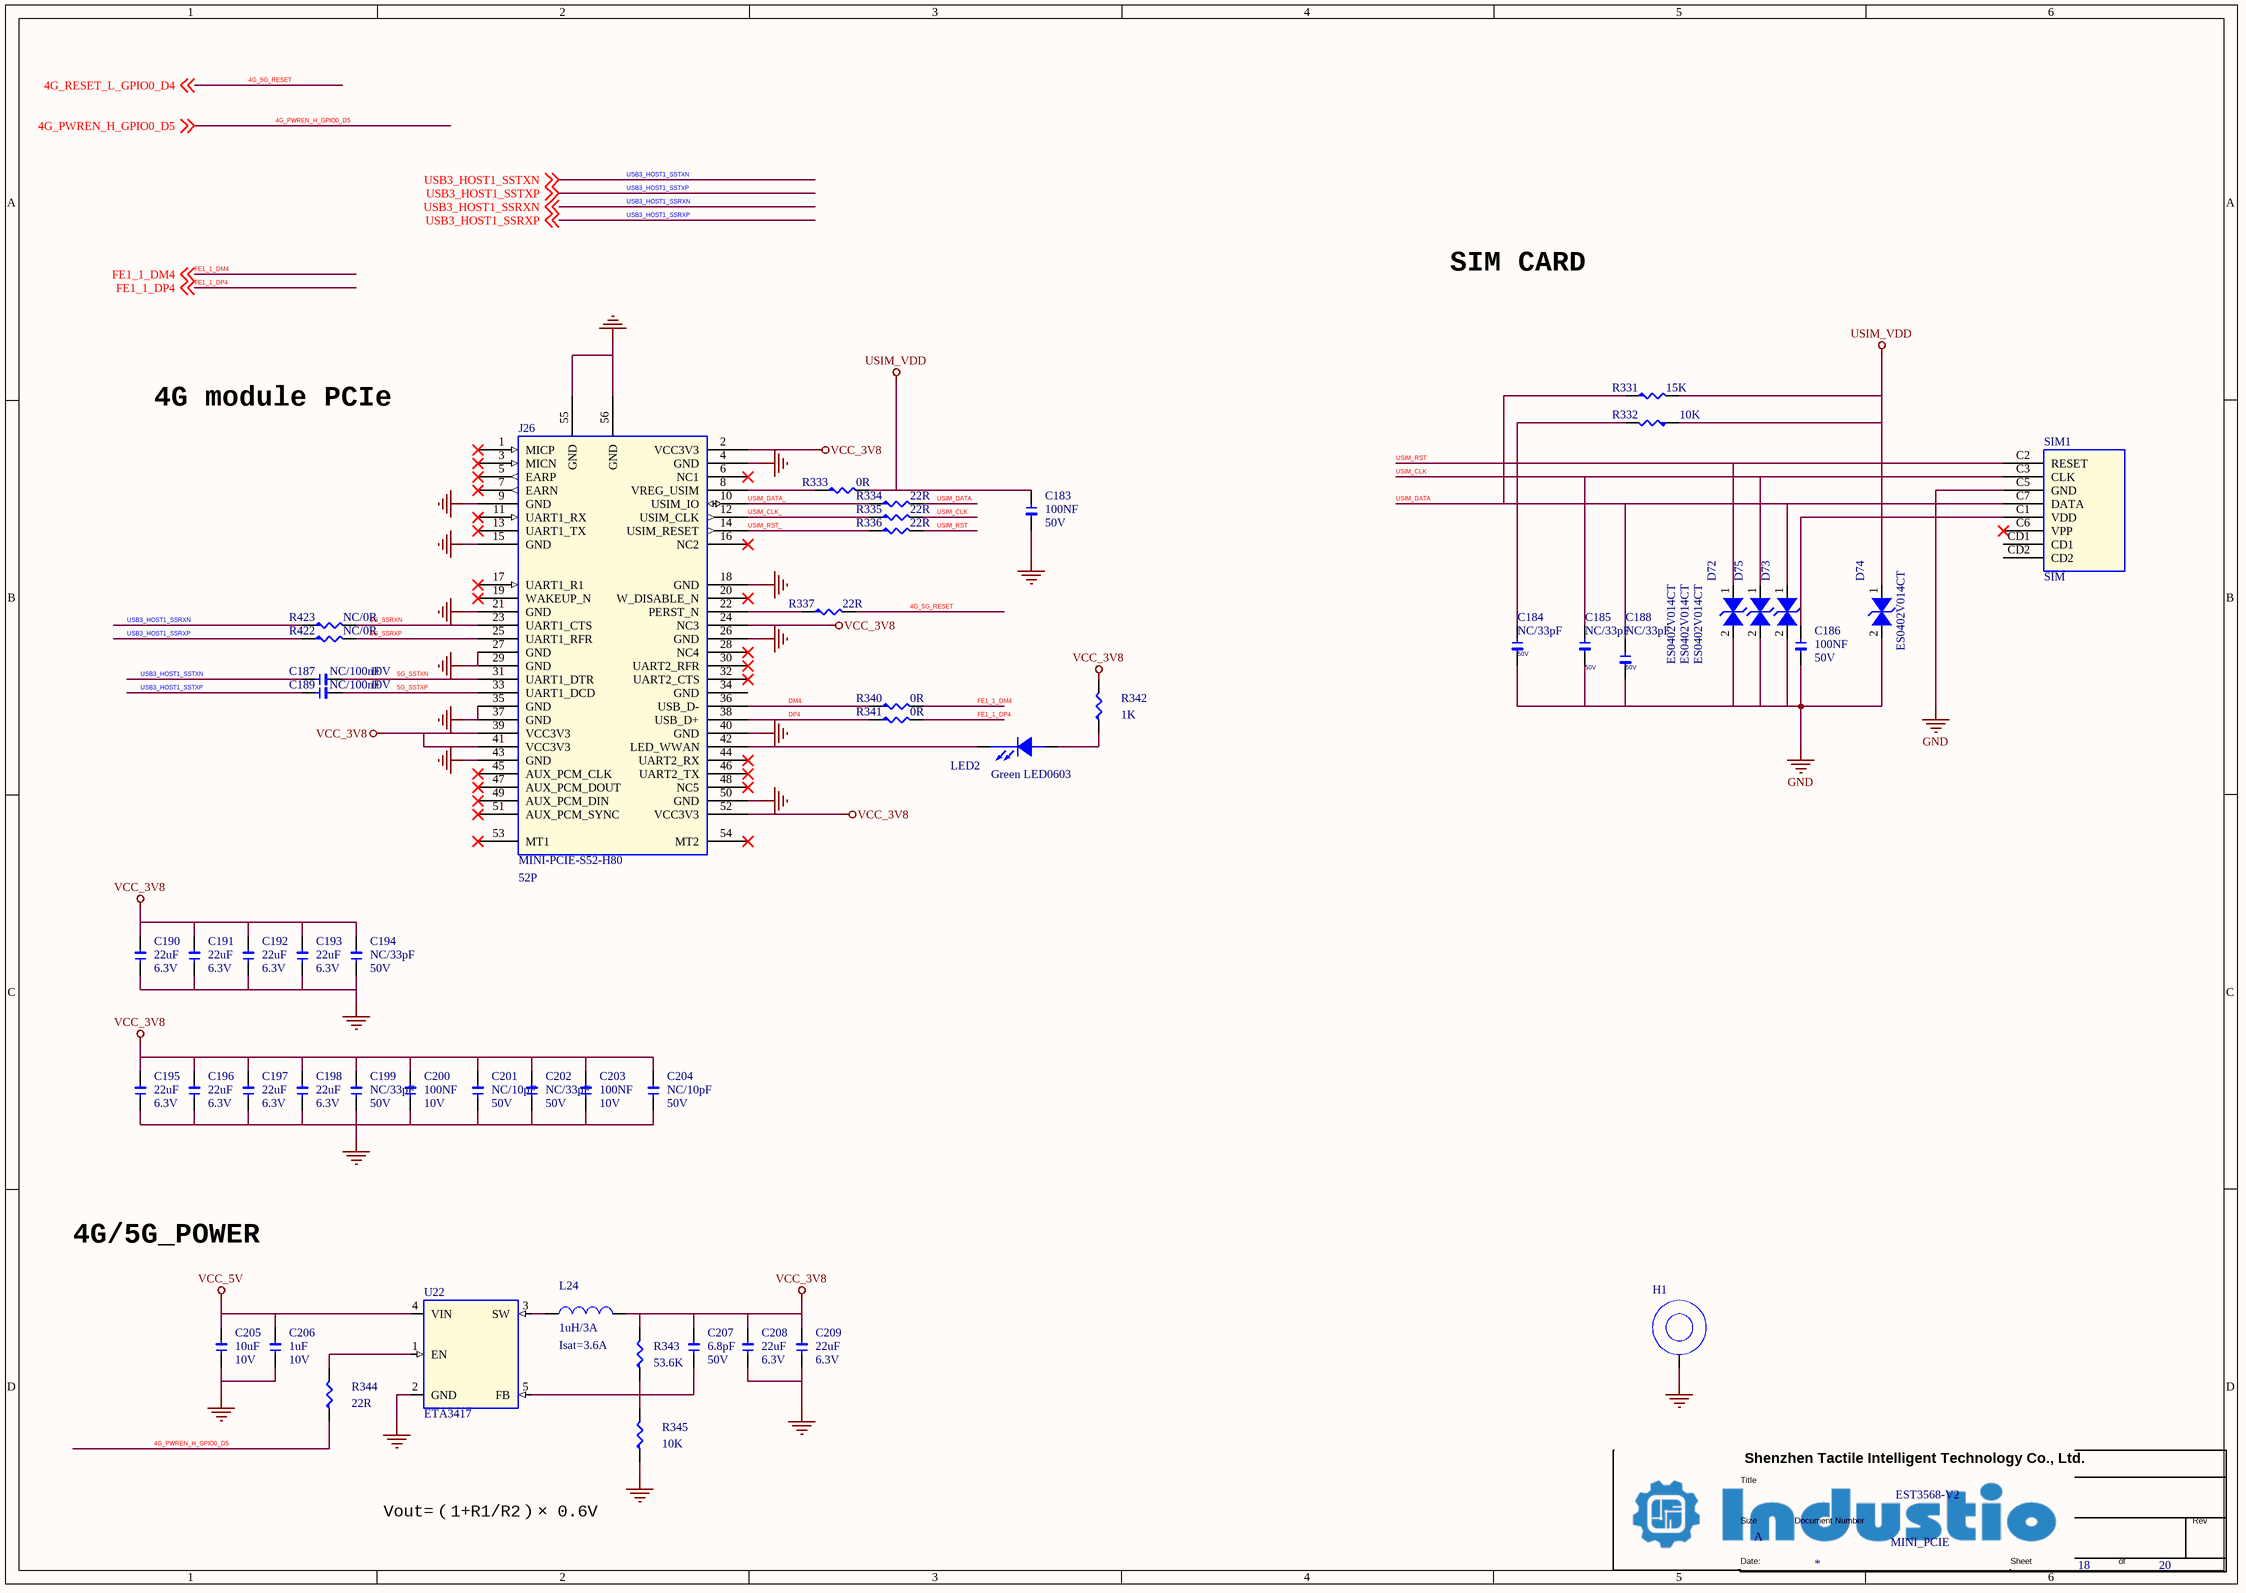
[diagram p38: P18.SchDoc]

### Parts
(Parts that share a designator on the sheet are numbered #1, #2 ... from top to bottom, then left to right.)
*#17  Doc: MINI_PCIE  Title: EST3568-V2  Page Size: A  Page Number: 18  Page Count: 20  (hidden comment: TitleBlock1)  (graphical)
C183  100NF  DSC2: 50V  [1206]
C184  NC/33pF  DSC2: 50V  [1206]
C185  NC/33pF  DSC2: 50V  [1206]
C186  100NF  DSC2: 50V  [1206]
C187  NC/100nF  DSC2: 10V  [1206]
C188  NC/33pF  DSC2: 50V  [1206]
C189  NC/100nF  DSC2: 10V  [1206]
C190  22uF  DSC2: 6.3V  [1206]
C191  22uF  DSC2: 6.3V  [1206]
C192  22uF  DSC2: 6.3V  [1206]
C193  22uF  DSC2: 6.3V  [1206]
C194  NC/33pF  DSC2: 50V  [1206]
C195  22uF  DSC2: 6.3V  [1206]
C196  22uF  DSC2: 6.3V  [1206]
C197  22uF  DSC2: 6.3V  [1206]
C198  22uF  DSC2: 6.3V  [1206]
C199  NC/33pF  DSC2: 50V  [1206]
C200  100NF  DSC2: 10V  [1206]
C201  NC/10pF  DSC2: 50V  [1206]
C202  NC/33pF  DSC2: 50V  [1206]
C203  100NF  DSC2: 10V  [1206]
C204  NC/10pF  DSC2: 50V  [1206]
C205  10uF  DSC2: 10V  [1206]
C206  1uF  DSC2: 10V  [1206]
C207  6.8pF  DSC2: 50V  [1206]
C208  22uF  DSC2: 6.3V  [1206]
C209  22uF  DSC2: 6.3V  [1206]
D72  ES0402V014CT  [V0402]
D73  ES0402V014CT  [V0402]
D74  ES0402V014CT  [V0402]
D75  ES0402V014CT  [V0402]
H1  Hole  [4G_MTG170_450]  (value not drawn)
J26  MINI-PCIE-S52-H80  DSC2: 52P  [M_MINIPCIE_SOCKET_CK]
L24  1uH/3A  DSC2: Isat=3.6A  [IND_252012]
LED2  Green LED0603  [LED0603]
R331  15K  [R0402]
R332  10K  [R0402]
R333  0R  [R0603]
R334  22R  [R0402]
R335  22R  [R0402]
R336  22R  [R0402]
R337  22R  [R0402]
R340  0R  [R0402]
R341  0R  [R0402]
R342  1K  [R0402]
R343  53.6K  [R0402]
R344  22R  [R0402]
R345  10K  [R0402]
R422  NC/0R  [R0402]
R423  NC/0R  [R0402]
SIM1  SIM  [SIM-91288-021]
U22  ETA3417  [SOT23-5]

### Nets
GND: C183.2 C184.2 C185.2 C186.2 C188.2 C190.1 C191.1 C192.1 C193.1 C194.1 C195.1 C196.1 C197.1 C198.1 C199.1 C200.1 C201.1 C202.1 C203.1 C204.1 C205.1 C206.1 C208.1 C209.1 D72.2(I/O1) D73.2(I/O1) D74.2(I/O1) D75.2(I/O1) H1.1 J26.4(GND) J26.9(GND) J26.15(GND) J26.18(GND) J26.21(GND) J26.26(GND) J26.27(GND) J26.29(GND) J26.35(GND) J26.37(GND) J26.40(GND) J26.43(GND) J26.50(GND) J26.55(GND) J26.56(GND) R345.1 SIM1.C5(GND) U22.2(GND)  [project net EDP_TX_AUXP_]
USIM_VDD: C183.1 C186.1 D74.1(I/O2) R331.2 R332.1 R333.2 SIM1.C1(VDD)
VCC_3V8: C190.2 C191.2 C192.2 C193.2 C194.2 C195.2 C196.2 C197.2 C198.2 C199.2 C200.2 C201.2 C202.2 C203.2 C204.2 C207.2 C208.2 C209.2 J26.2(VCC3V3) J26.24(NC3) J26.39(VCC3V3) J26.41(VCC3V3) J26.52(VCC3V3) L24.2 R342.2 R343.2
VCC_5V: C205.2 C206.2 U22.4(VIN)
4G_5G_RESET: R337.2 ; off-sheet 4G_RESET_L_GPIO0_D4  [also labelled 4G_RESET_L_GPIO0_D4]
4G_PWREN_H_GPIO0_D5: R344.1 ; off-sheet 4G_PWREN_H_GPIO0_D5
5G_SSRXN: J26.23(UART1_CTS) R423.2
5G_SSRXP: J26.25(UART1_RFR) R422.2
5G_SSTXN: C187.2 J26.31(UART1_DTR)
5G_SSTXP: C189.2 J26.33(UART1_DCD)
DM4: J26.36(USB_D-) R340.1
DP4: J26.38(USB_D+) R341.1
FE1_1_DM4: R340.2 ; off-sheet FE1_1_DM4
FE1_1_DP4: R341.2 ; off-sheet FE1_1_DP4
USB3_HOST1_SSRXN: R423.1 ; off-sheet USB3_HOST1_SSRXN
USB3_HOST1_SSRXP: R422.1 ; off-sheet USB3_HOST1_SSRXP
USB3_HOST1_SSTXN: C187.1 ; off-sheet USB3_HOST1_SSTXN
USB3_HOST1_SSTXP: C189.1 ; off-sheet USB3_HOST1_SSTXP
USIM_CLK: C185.1 D75.1(I/O2) R335.2 SIM1.C3(CLK)
USIM_CLK_: J26.12(USIM_CLK) R335.1
USIM_DATA: C188.1 D73.1(I/O2) R331.1 R334.2 SIM1.C7(DATA)
USIM_DATA_: J26.10(USIM_IO) R334.1
USIM_RST: C184.1 D72.1(I/O2) R332.2 R336.2 SIM1.C2(RESET)
USIM_RST_: J26.14(USIM_RESET) R336.1
NetC207_1: C207.1 R343.1 R345.2 U22.5(FB)
NetJ26_8: J26.8(VREG_USIM) R333.1
NetJ26_22: J26.22(PERST_N) R337.1
NetJ26_42: J26.42(LED_WWAN) LED2.2(CATHODE)
NetL24_1: L24.1 U22.3(SW)
NetLED2_1: LED2.1(ANODE) R342.1
NetR344_2: R344.2 U22.1(EN)

Not connected (* = marked no-connect by the designer): J26 1(MICP)* 3(MICN)* 5(EARP)* 6(NC1)* 7(EARN)* 11(UART1_RX)* 13(UART1_TX)* 16(NC2)* 17(UART1_R1)* 19(WAKEUP_N)* 20(W_DISABLE_N)* 28(NC4)* 30(UART2_RFR)* 32(UART2_CTS)* 34(GND) 44(UART2_RX)* 45(AUX_PCM_CLK)* 46(UART2_TX)* 47(AUX_PCM_DOUT)* 48(NC5)* 49(AUX_PCM_DIN)* 51(AUX_PCM_SYNC)* 53(MT1)* 54(MT2)*; SIM1 C6(VPP)* CD1 CD2

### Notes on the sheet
- SIM CARD
- 4G module PCIe
- 4G/5G_POWER
- Vout=（1+R1/R2）× 0.6V

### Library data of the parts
C183 = C-0402_Dup2: Part Number: C020102120061; Part Name: 贴片电容; Manufacture: 三星¦国巨¦村田; ERP Number: 1010200128; DSC1: ±10%; DSC3: X7R; ID: 61; PCB Footprint: C0402
C184 C185 = C-0402: Manufacture: 三星¦国巨¦村田; Part Name: 贴片电容; Part Number: C020102120033; PCB Footprint: C0402; DSC3: C0G; DSC1: ±5%; ERP Number: 1010200087
C186 = C-0402_Dup2: Manufacture: 三星¦国巨¦村田; Part Name: 贴片电容; Part Number: C020102120061; ID: 61; DSC3: X7R; DSC1: ±10%; ERP Number: 1010200128; PCB Footprint: C0402
C187 C189 = C-0402_Dup2: as C161-C163 on sheet P15
C188 = C-0402: Part Number: C020102120033; Part Name: 贴片电容; Manufacture: 三星¦国巨¦村田; PCB Footprint: C0402; ERP Number: 1010200087; DSC1: ±5%; DSC3: C0G
C190-C193 C195-C198 = C-0603_Dup2: Part Number: C020102120072; Part Name: 贴片电容; Manufacture: 三星¦国巨¦村田; ERP Number: 1010200133; DSC1: ±20%; DSC3: X5R; ID: 72; PCB Footprint: C0603
C194 C199 C202 = C-0402_Dup2: Manufacture: 三星¦国巨¦村田; Part Name: 贴片电容; Part Number: C020102120033; PCB Footprint: C0402; ID: 33; DSC3: C0G; DSC1: ±5%; ERP Number: 1010200087
C200 C203 = C-0402_Dup2: as C123 on sheet P13
C201 C204 = C-0402_Dup2: Manufacture: 三星¦国巨¦村田; Part Name: 贴片电容; Part Number: C020102120021; PCB Footprint: C0402; ID: 21; DSC3: C0G; DSC1: ±5%; ERP Number: 1010200151
C205 = C-0603_Dup2: Part Number: C020102120071; Part Name: 贴片电容; Manufacture: 三星¦国巨¦村田; PCB Footprint: C0603; ERP Number: 1010200076; DSC1: ±20%; DSC3: X5R; ID: 71
C206 = C-0402_Dup2: as C169 on sheet P15
C207 = C-0402_Dup2: as C155 on sheet P15
C208 = C-0603_Dup1: Part Number: C020102120072; Part Name: 贴片电容; Manufacture: 三星¦国巨¦村田; PCB Footprint: C0603; ERP Number: 1010200133; DSC1: ±20%; DSC3: X5R; ID: 72
C209 = C-0603_Dup1: Manufacture: 三星¦国巨¦村田; Part Name: 贴片电容; Part Number: C020102120072; PCB Footprint: C0603; ID: 72; DSC3: X5R; DSC1: ±20%; ERP Number: 1010200133
D72-D75 = DI-ESD_Dup1: as D71 on sheet P17
J26 = J-MINIPCIE-52P_1: Part Name: 金手指连接器; Part Number: J050102900003; CLASS: IO; ID: 3; DSC4: 91304-80-052R2(UMaxconn); DSC3: 贴片; DSC1: mini pcie 52P 8.0H 镀金G/F
L24 = L-IND: Part Name: 功率电感; Manufacture: 宗成¦长江微电¦顺络; DSC1: ±20%; DSC3: Irms=3A; DSC4: 54mΩ; DSC5: 2.5*2.0*1.2mm; DSC6: WPN252012H1R0MT(顺络); DSC7: FHD252012S-1R0MT(长江微电); DSC8: ZCRH252012-1uH-M(宗成); ID: 52
LED2 = D-LED0603_0: Part Name: LED; Part Number: C140202660003; ID: 7; DSC3: 19-217/GHC-YR1S2/3T(亿光); DSC2: NCD0603G1(国星光电); DSC1: 绿色LED，SMD,0603，VF=3V; ERP Number: 1010800009
R331 = R-0402_Dup4: Part Number: C011002080332; Part Name: 贴片电阻; ID: 332; DSC2: 1/16W; DSC1: ±5%; ERP Number: 1010200258
R332 = R-0402_Dup4: as R398 on sheet P16
R333 = R-0603_Dup1: Part Name: 贴片电阻; Part Number: C011002081182; ERP Number: 1010200158; DSC1: ±1%; DSC2: 1/10W; ID: 1,182
R334 R335 = R-0402_Dup4: as R181-R184 on sheet P13
R336 R337 R344 = R-0402_Dup4: as R224 on sheet P14
R340 R341 = R-0402_Dup4: as R191 on sheet P13
R342 = R-0402_Dup4: Part Number: C011002080303; Part Name: 贴片电阻; ID: 303; DSC2: 1/16W; DSC1: ±5%; ERP Number: 1010200104
R343 = R-0402_Dup4: Part Number: C011002080943; Part Name: 贴片电阻; ID: 943; DSC2: 1/16W; DSC1: ±1%
R345 = R-0402_Dup4: Part Number: C011002080856; Part Name: 贴片电阻; ID: 856; DSC2: 1/16W; DSC1: ±1%; ERP Number: 1010200140
R422 R423 = R-0402_Dup4: as R205 on sheet P13
SIM1 = J-SIM-021_0: Part Number: J080202990002; Part Name: SIM卡座; ERP Number: 1040100109; DSC1: SIM卡座 91228 抽屉式 8P; DSC2: 31.0*25.1*26mm; DSC3: 贴片; DSC4: SIM-021(硕方); ID: 5
U22 = U-ETA3417_1: Manufacture: 钰泰; Part Number: C070205183984; Part Name: DCDC; ID: 43; Solder: 量产; DSC8: 替代料：TI的TLV62569DBVR/矽力杰SY8089AAAC; DSC7: 同步降压; DSC6: 3MHz; DSC4: Vfb=0.6V; DSC3: Io=2.5A; DSC2: Vo=0.6-7.0V; DSC1: Vi=2.6-7.0V

## Sheet P19.SchDoc
size 420 x 297 mm
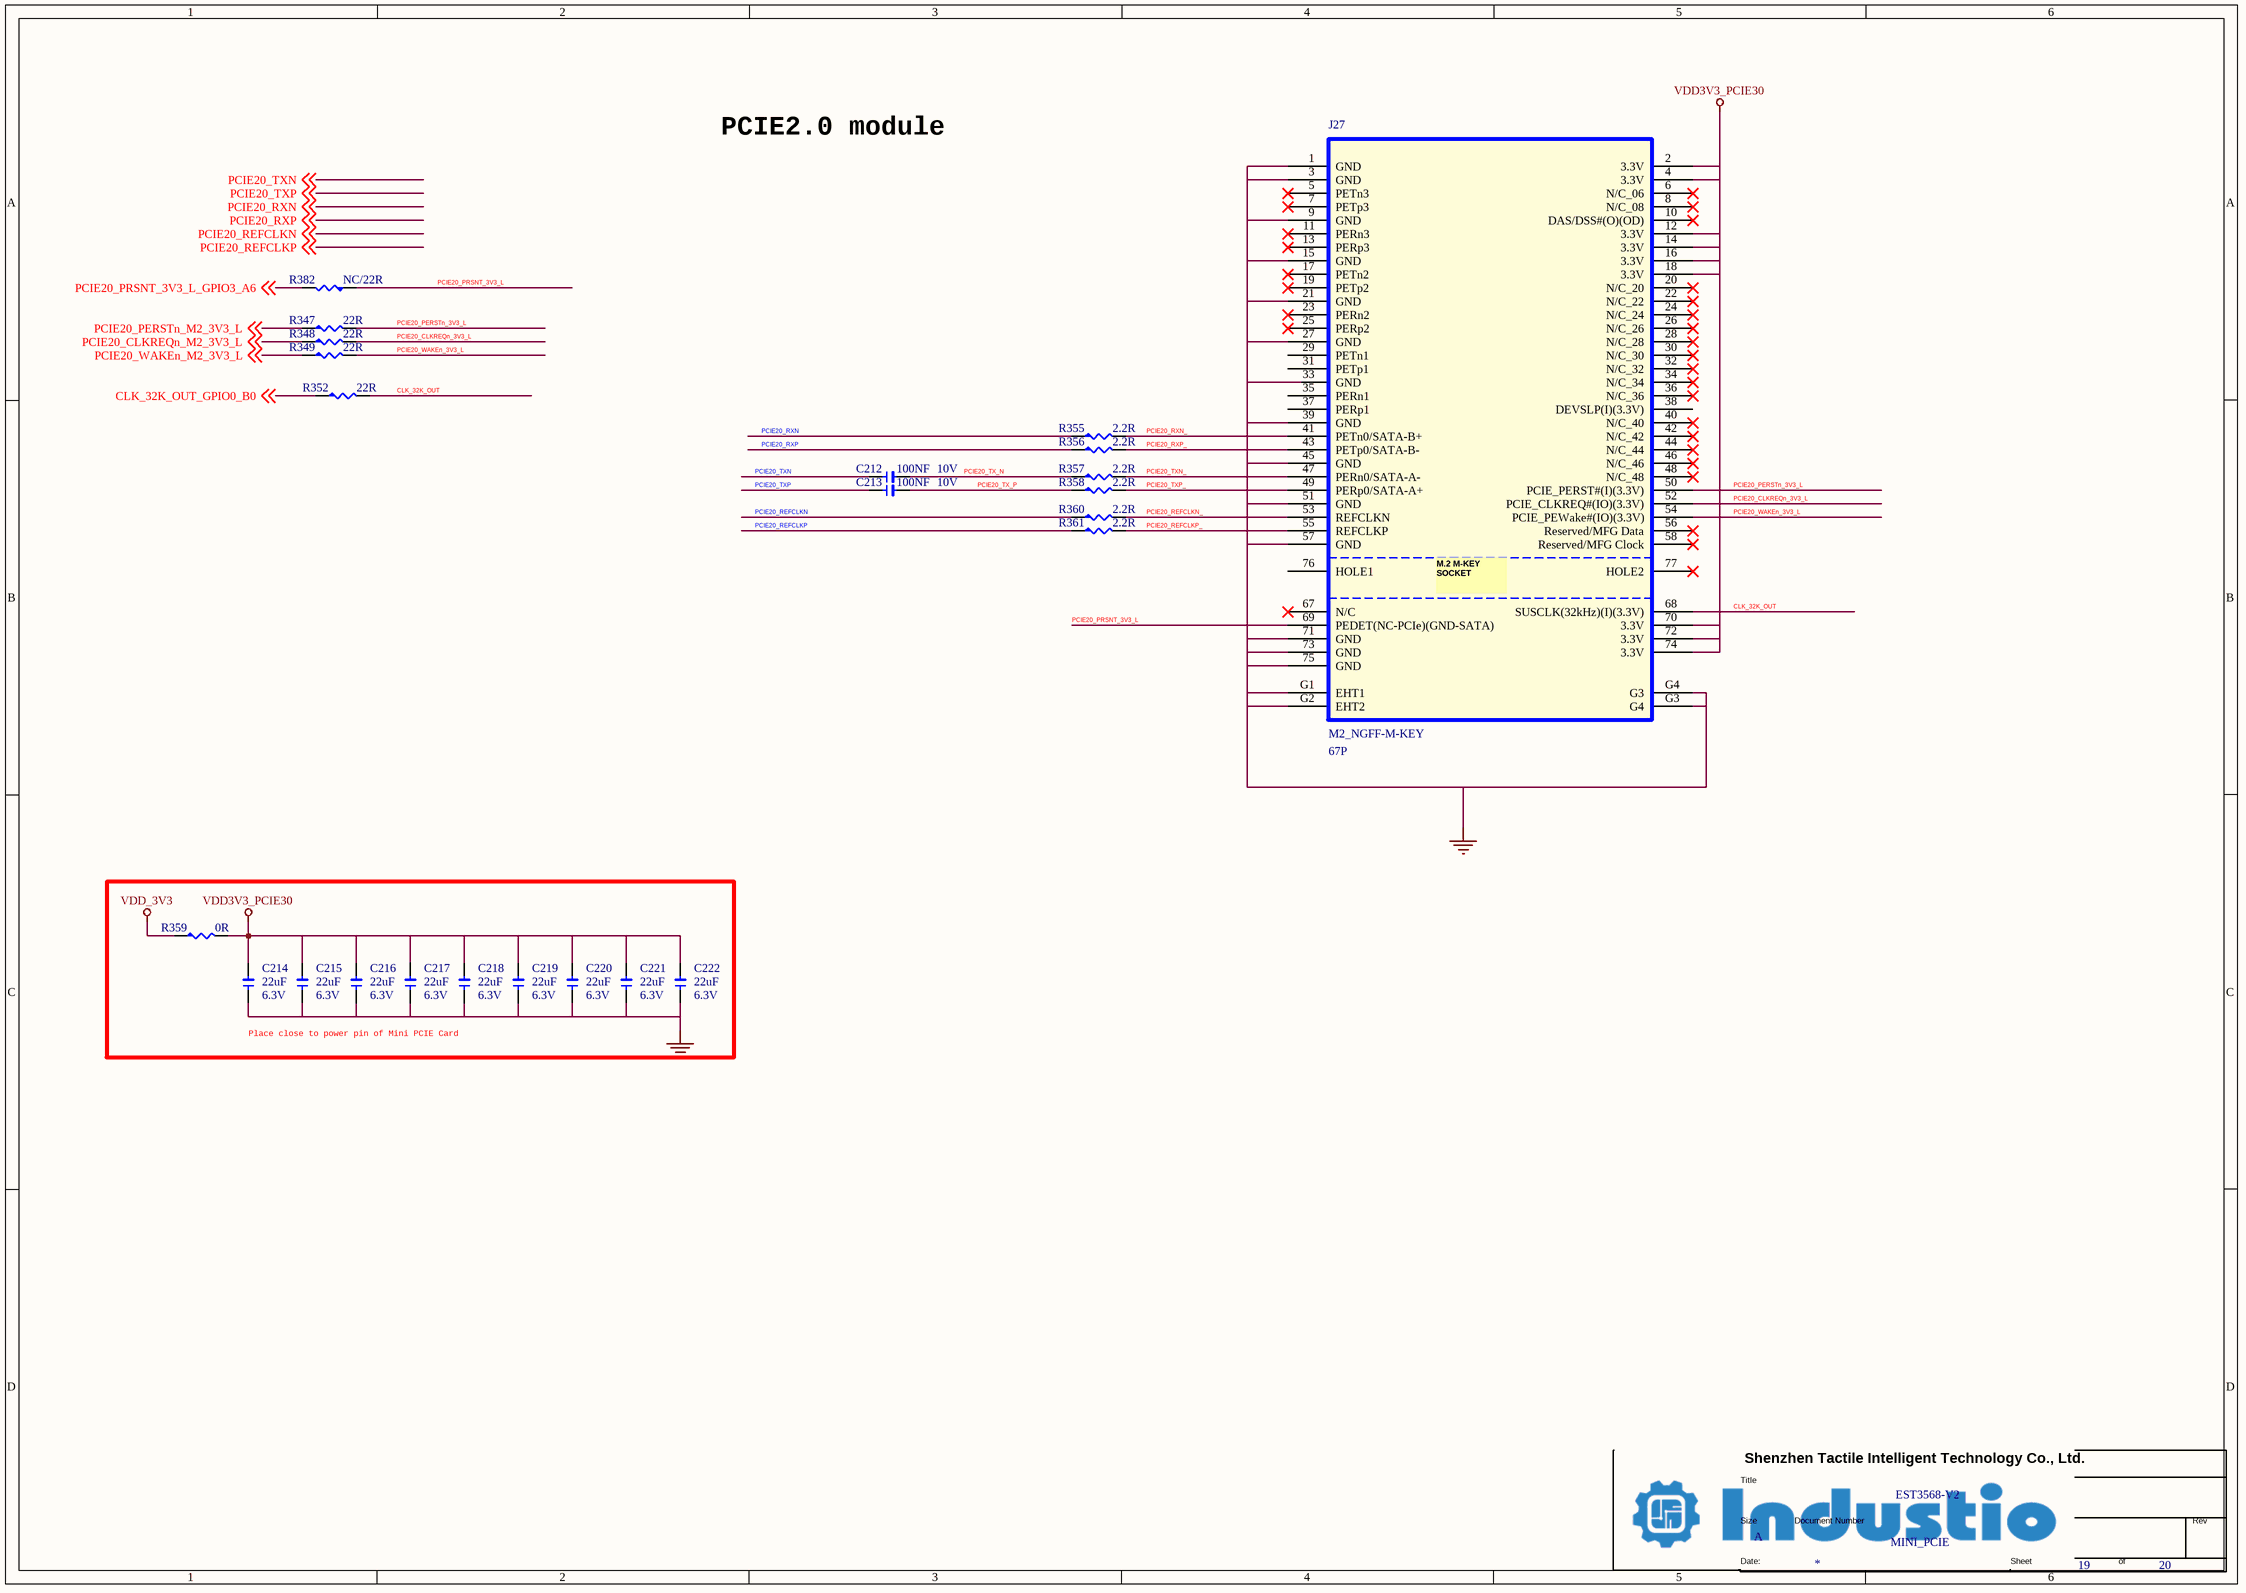
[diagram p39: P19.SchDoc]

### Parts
(Parts that share a designator on the sheet are numbered #1, #2 ... from top to bottom, then left to right.)
*#18  Doc: MINI_PCIE  Title: EST3568-V2  Page Size: A  Page Number: 19  Page Count: 20  (hidden comment: TitleBlock1)  (graphical)
C212  100NF  DSC2: 10V  [1206]
C213  100NF  DSC2: 10V  [1206]
C214  22uF  DSC2: 6.3V  [1206]
C215  22uF  DSC2: 6.3V  [1206]
C216  22uF  DSC2: 6.3V  [1206]
C217  22uF  DSC2: 6.3V  [1206]
C218  22uF  DSC2: 6.3V  [1206]
C219  22uF  DSC2: 6.3V  [1206]
C220  22uF  DSC2: 6.3V  [1206]
C221  22uF  DSC2: 6.3V  [1206]
C222  22uF  DSC2: 6.3V  [1206]
J27  M2_NGFF-M-KEY  DSC2: 67P  [M2_NGFF-M-KEY]
R347  22R  [R0402]
R348  22R  [R0402]
R349  22R  [R0402]
R352  22R  [R0402]
R355  2.2R  [R0402]
R356  2.2R  [R0402]
R357  2.2R  [R0402]
R358  2.2R  [R0402]
R359  0R  [R0603]
R360  2.2R  [R0402]
R361  2.2R  [R0402]
R382  NC/22R  [R0402]

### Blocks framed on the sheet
Place close to power pin of Mini PCIE Card: C214-C222 R359

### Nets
GND: C214.1 C215.1 C216.1 C217.1 C218.1 C219.1 C220.1 C221.1 C222.1 J27.1(GND) J27.3(GND) J27.9(GND) J27.15(GND) J27.21(GND) J27.27(GND) J27.33(GND) J27.39(GND) J27.45(GND) J27.51(GND) J27.57(GND) J27.71(GND) J27.73(GND) J27.75(GND) J27.G1(EHT1) J27.G2(EHT2) J27.G3(G4) J27.G4(G3)  [project net EDP_TX_AUXP_]
VDD3V3_PCIE30: C214.2 C215.2 C216.2 C217.2 C218.2 C219.2 C220.2 C221.2 C222.2 J27.2(3.3V) J27.4(3.3V) J27.12(3.3V) J27.14(3.3V) J27.16(3.3V) J27.18(3.3V) J27.70(3.3V) J27.72(3.3V) J27.74(3.3V) R359.2
VDD_3V3: R359.1
CLK_32K_OUT: J27.68(SUSCLK(32kHz)(I)(3.3V)) R352.2
CLK_32K_OUT_GPIO0_B0: R352.1 ; off-sheet CLK_32K_OUT_GPIO0_B0
PCIE20_CLKREQn_3V3_L: J27.52(PCIE_CLKREQ#(IO)(3.3V)) R348.2
PCIE20_CLKREQn_M2_3V3_L: R348.1 ; off-sheet PCIE20_CLKREQn_M2_3V3_L
PCIE20_PERSTn_3V3_L: J27.50(PCIE_PERST#(I)(3.3V)) R347.2
PCIE20_PERSTn_M2_3V3_L: R347.1 ; off-sheet PCIE20_PERSTn_M2_3V3_L
PCIE20_PRSNT_3V3_L: J27.69(PEDET(NC-PCIe)(GND-SATA)) R382.1
PCIE20_PRSNT_3V3_L_GPIO3_A6: R382.2 ; off-sheet PCIE20_PRSNT_3V3_L_GPIO3_A6
PCIE20_REFCLKN: R360.1 ; off-sheet PCIE20_REFCLKN
PCIE20_REFCLKN_: J27.53(REFCLKN) R360.2
PCIE20_REFCLKP: R361.1 ; off-sheet PCIE20_REFCLKP
PCIE20_REFCLKP_: J27.55(REFCLKP) R361.2
PCIE20_RXN: R355.1 ; off-sheet PCIE20_RXN
PCIE20_RXN_: J27.41(PETn0/SATA-B+) R355.2
PCIE20_RXP: R356.1 ; off-sheet PCIE20_RXP
PCIE20_RXP_: J27.43(PETp0/SATA-B-) R356.2
PCIE20_TX_N: C212.2 R357.1
PCIE20_TX_P: C213.2 R358.1
PCIE20_TXN: C212.1 ; off-sheet PCIE20_TXN
PCIE20_TXN_: J27.47(PERn0/SATA-A-) R357.2
PCIE20_TXP: C213.1 ; off-sheet PCIE20_TXP
PCIE20_TXP_: J27.49(PERp0/SATA-A+) R358.2
PCIE20_WAKEn_3V3_L: J27.54(PCIE_PEWake#(IO)(3.3V)) R349.2
PCIE20_WAKEn_M2_3V3_L: R349.1 ; off-sheet PCIE20_WAKEn_M2_3V3_L

Not connected (* = marked no-connect by the designer): J27 5(PETn3)* 6(N/C_06)* 7(PETp3)* 8(N/C_08)* 10(DAS/DSS#(O)(OD))* 11(PERn3)* 13(PERp3)* 17(PETn2)* 19(PETp2)* 20(N/C_20)* 22(N/C_22)* 23(PERn2)* 24(N/C_24)* 25(PERp2)* 26(N/C_26)* 28(N/C_28)* 29(PETn1) 30(N/C_30)* 31(PETp1) 32(N/C_32)* 34(N/C_34)* 35(PERn1) 36(N/C_36)* 37(PERp1) 38(DEVSLP(I)(3.3V)) 40(N/C_40)* 42(N/C_42)* 44(N/C_44)* 46(N/C_46)* 48(N/C_48)* 56(Reserved/MFG_Data)* 58(Reserved/MFG_Clock)* 67(N/C)* 76(HOLE1) 77(HOLE2)*

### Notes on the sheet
- PCIE2.0 module

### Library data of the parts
C212 C213 = C-0402_Dup1: Manufacture: 三星¦国巨¦村田; Part Name: 贴片电容; Part Number: C020102120060; ID: 60; DSC3: X7R; DSC1: ±10%; PCB Footprint: C0402
C214 C215 C217 = C-0603_Dup2: as C190 on sheet P18
C216 C218-C222 = C-0603_Dup2: as C118 on sheet P13
J27 = J-M2_NGFF-M-KEY_1: Part Name: 金手指连接器; Part Number: J050111093948; ID: 31; DSC5: APCI0164-P001A(LOTES); DSC4: 91302-85-067RDM(Umaxconn); DSC3: 贴片; DSC1: M2_NGFF-M座子,0.5mm Pitch,H=8.5mm
R347-R349 R352 = R-0402_Dup4: as R224 on sheet P14
R355-R358 = R-0402_Dup4: as R259-R266 on sheet P15
R359 = R-0603: Part Name: 贴片电阻; Part Number: C011002081182; ERP Number: 1010200158; DSC1: ±1%; DSC2: 1/10W; ID: 1,182
R360 R361 = R-0402_Dup4: as R214 on sheet P14
R382 = R-0402_Dup4: as R181-R184 on sheet P13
